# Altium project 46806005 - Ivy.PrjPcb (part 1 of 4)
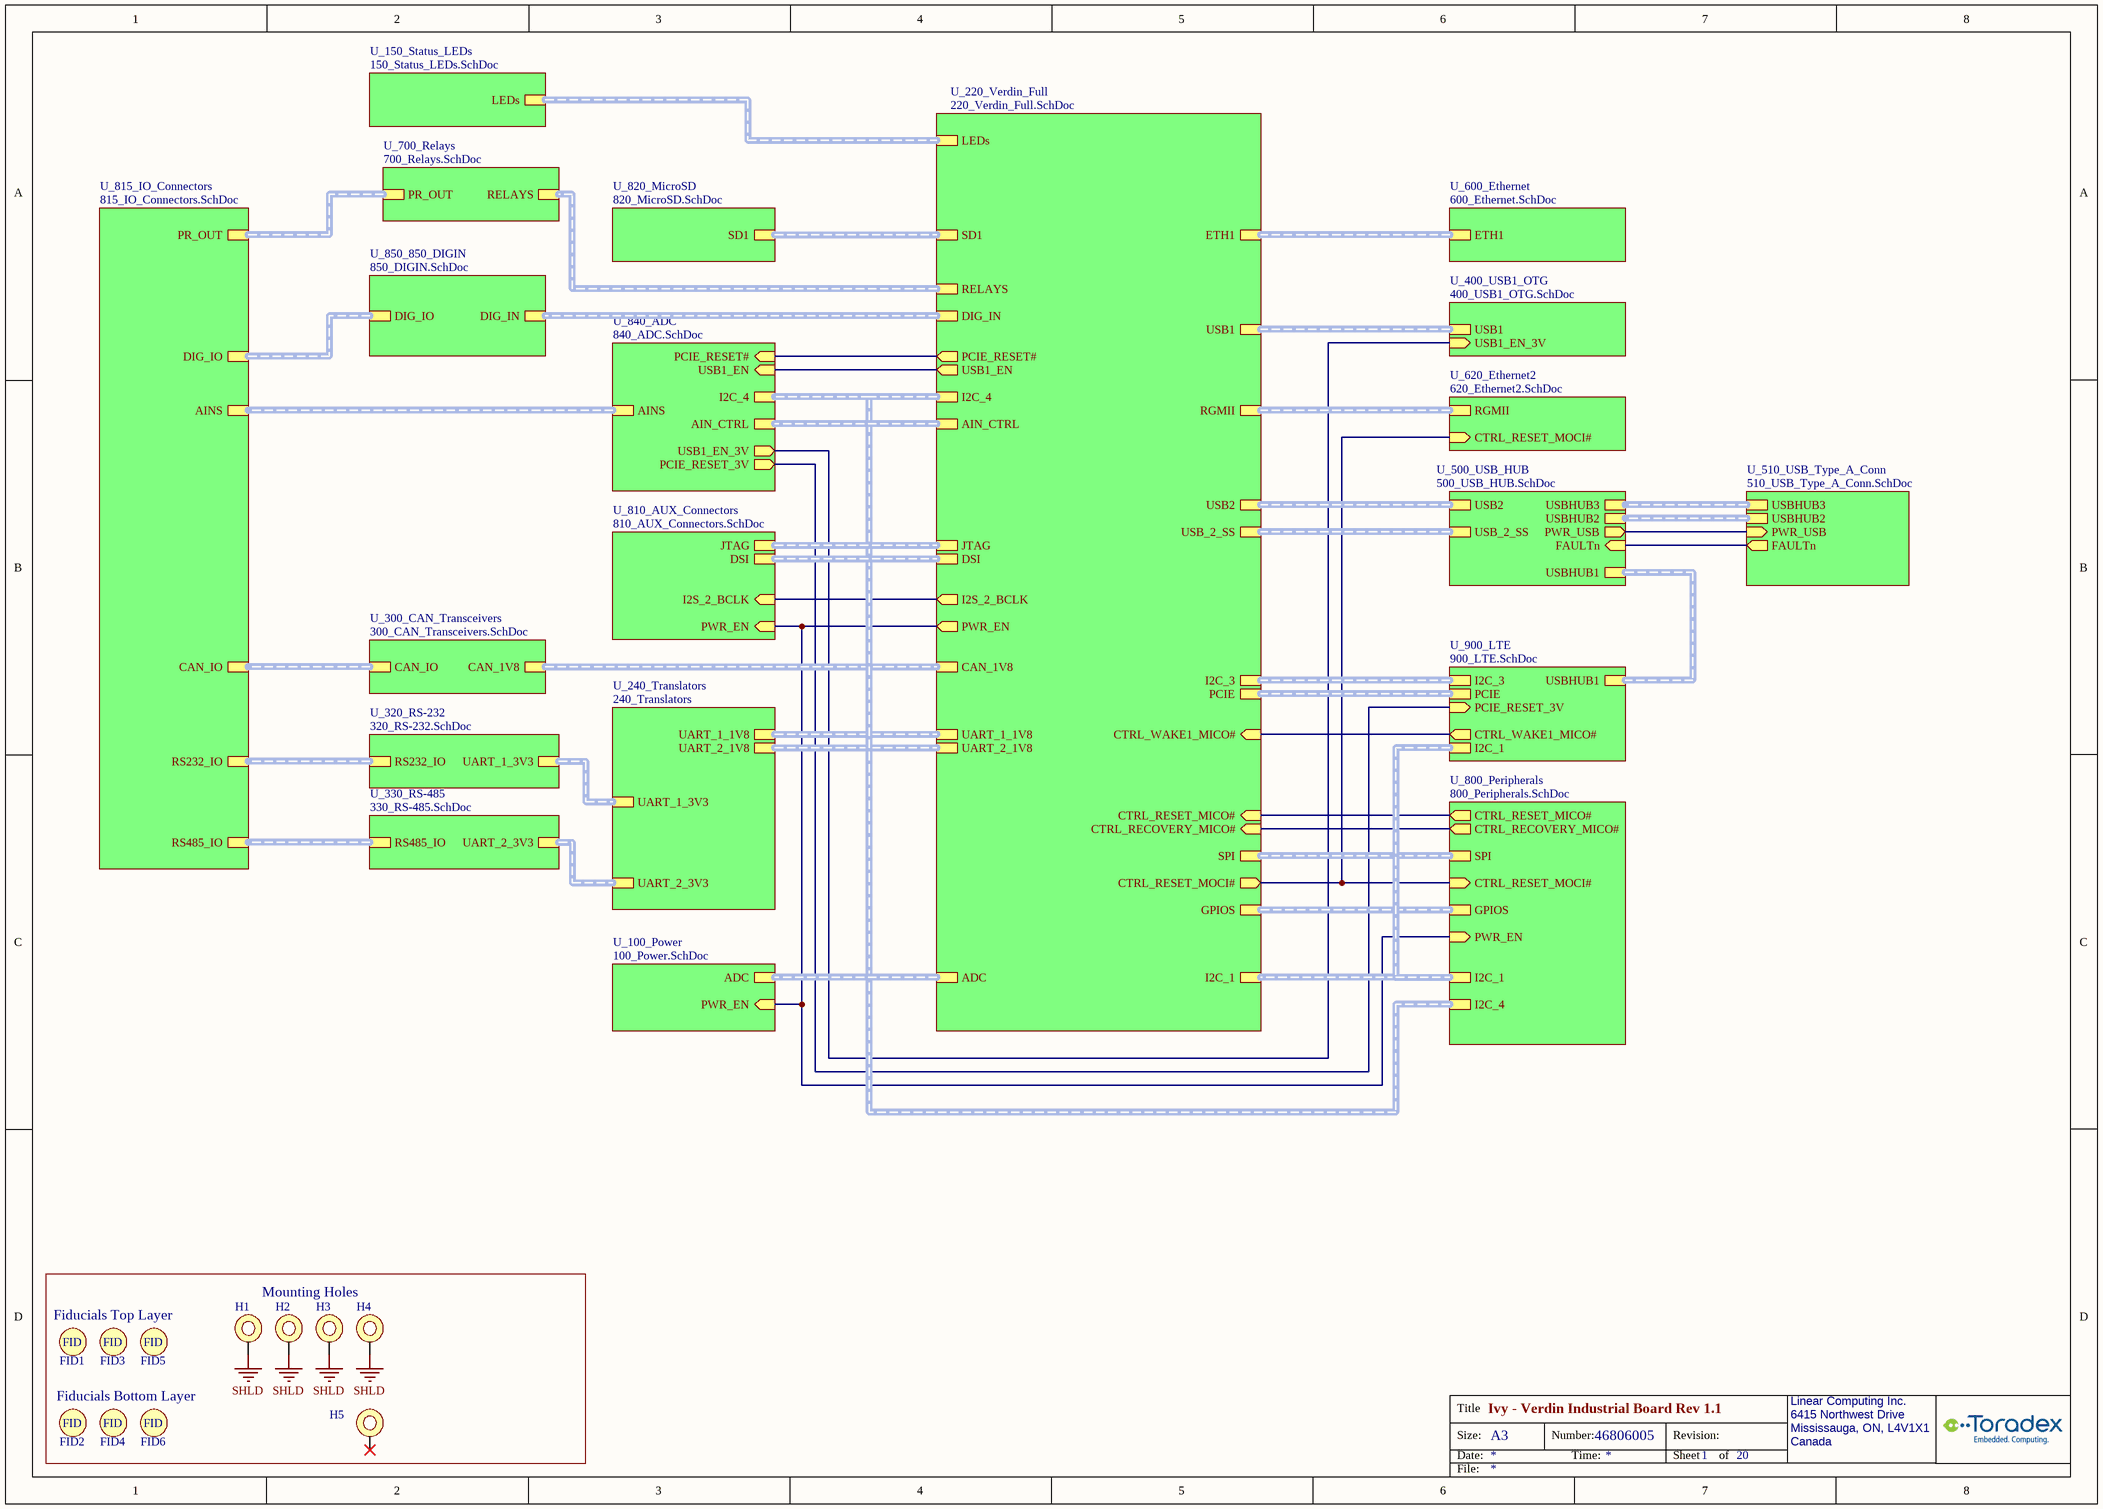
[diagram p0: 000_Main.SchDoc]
CompanyName: Toradex Solutions Inc.; DocumentNumber: 46806005; Title: Ivy - Verdin Industrial Board Rev 1.1
21 sheets, 800 parts. Net scope: hierarchical (ports join the sheet entries above them; power ports are global).
Board file: 46806005.PcbDoc
Sheets:
  000_Main.SchDoc
    U_100_Power = 100_Power.SchDoc
    U_600_Ethernet = 600_Ethernet.SchDoc
    U_400_USB1_OTG = 400_USB1_OTG.SchDoc
    U_220_Verdin_Full = 220_Verdin_Full.SchDoc
    U_800_Peripherals = 800_Peripherals.SchDoc
    U_240_Translators = 240_Translators.SchDoc
    U_900_LTE = 900_LTE.SchDoc
    U_300_CAN_Transceivers = 300_CAN_Transceivers.SchDoc
    U_500_USB_HUB = 500_USB_Hub.SchDoc
    U_700_Relays = 700_Relays.SchDoc
    U_150_Status_LEDs = 150_Status_LEDs.SchDoc
    U_620_Ethernet2 = 620_Ethernet2.SchDoc
    U_820_MicroSD = 820_MicroSD.SchDoc
    U_840_ADC = 840_ADC.SchDoc
    U_320_RS-232 = 320_RS-232.SchDoc
    U_330_RS-485 = 330_RS-485.SchDoc
    U_850_850_DIGIN = 850_DIGIN.SchDoc
    U_810_AUX_Connectors = 810_AUX_Connectors.SchDoc
    U_510_USB_Type_A_Conn = 510_USB_Type_A_Conn.SchDoc
    U_815_IO_Connectors = 815_IO_Connectors.SchDoc

## Sheet 000_Main.SchDoc: Ivy - Verdin Industrial Board Rev 1.1
size A3; Organization: Linear Computing Inc.; Address1: 6415 Northwest Drive; Address2: Mississauga, ON, L4V1X1; Address3: Canada; SheetNumber: 1; SheetTotal: 20

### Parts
FID1  Fiducial round  [FID_40X120_RND]  (value not drawn)  (no BOM)
FID2  Fiducial round  [FID_40X120_RND]  (value not drawn)  (no BOM)
FID3  Fiducial round  [FID_40X120_RND]  (value not drawn)  (no BOM)
FID4  Fiducial round  [FID_40X120_RND]  (value not drawn)  (no BOM)
FID5  Fiducial round  [FID_40X120_RND]  (value not drawn)  (no BOM)
FID6  Fiducial round  [FID_40X120_RND]  (value not drawn)  (no BOM)
H1  Hole  [MTG_HOLE_0.125]  (value not drawn)  (no BOM)
H2  Hole  [MTG_HOLE_0.125]  (value not drawn)  (no BOM)
H3  Hole  [MTG_HOLE_0.125]  (value not drawn)  (no BOM)
H4  Hole  [MTG_HOLE_0.125]  (value not drawn)  (no BOM)
H5  Hole  [MTG_HOLE_0.125]  (value not drawn)  (no BOM)

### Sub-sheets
U_100_Power = 100_Power.SchDoc: PWR_EN (in), ADC (harness ADC)
U_150_Status_LEDs = 150_Status_LEDs.SchDoc: LEDs (harness LEDs)
U_220_Verdin_Full = 220_Verdin_Full.SchDoc: CTRL_RECOVERY_MICO# (in), CTRL_RESET_MICO# (in), CTRL_WAKE1_MICO# (in), ETH1 (harness ETH1), USB2 (harness USB2), USB1 (harness USB1), PCIE (harness PCIe), SPI (harness SPI), PWR_EN (out), AIN_CTRL (harness AIN_CTRL), CTRL_RESET_MOCI# (out), GPIOS (harness GPIOs), RGMII (harness RGMII), SD1 (harness SD1), CAN_1V8 (harness 2xCAN_1V8), UART_1_1V8 (harness UART_1_1V8), UART_2_1V8 (harness UART_2_1V8), RELAYS (harness RELAYS), I2C_1 (harness I2C_1), DIG_IN (harness DIG_IN), JTAG (harness JTAG), LEDs (harness LEDs), I2C_4 (harness I2C_4), DSI (harness DSI), I2S_2_BCLK (out), ADC (harness ADC), I2C_3 (harness I2C_3), USB1_EN (out), PCIE_RESET# (out), USB_2_SS (harness USB_2_SS)
U_240_Translators = 240_Translators: UART_1_1V8 (harness UART_1_1V8), UART_2_1V8 (harness UART_2_1V8), UART_2_3V3 (harness UART_2_3V3), UART_1_3V3 (harness UART_1_3V3)
U_300_CAN_Transceivers = 300_CAN_Transceivers.SchDoc: CAN_1V8 (harness 2xCAN_1V8), CAN_IO (harness CAN_IO)
U_320_RS-232 = 320_RS-232.SchDoc: UART_1_3V3 (harness UART_1_3V3), RS232_IO (harness RS232_IO)
U_330_RS-485 = 330_RS-485.SchDoc: UART_2_3V3 (harness UART_2_3V3), RS485_IO (harness RS485_IO)
U_400_USB1_OTG = 400_USB1_OTG.SchDoc: USB1_EN_3V (in), USB1 (harness USB1)
U_500_USB_HUB = 500_USB_HUB.SchDoc: USB2 (harness USB2), USBHUB1 (harness USBHUB1), USBHUB2 (harness USBHUB2), USBHUB3 (harness USBHUB3), PWR_USB (out), FAULTn (in), USB_2_SS (harness USB_2_SS)
U_510_USB_Type_A_Conn = 510_USB_Type_A_Conn.SchDoc: USBHUB2 (harness USBHUB2), USBHUB3 (harness USBHUB3), PWR_USB (in), FAULTn (out)
U_600_Ethernet = 600_Ethernet.SchDoc: ETH1 (harness ETH1)
U_620_Ethernet2 = 620_Ethernet2.SchDoc: RGMII (harness RGMII), CTRL_RESET_MOCI# (in)
U_700_Relays = 700_Relays.SchDoc: RELAYS (harness RELAYS), PR_OUT (harness PR_OUT)
U_800_Peripherals = 800_Peripherals.SchDoc: CTRL_RECOVERY_MICO# (out), CTRL_RESET_MICO# (out), I2C_1 (harness I2C_1), SPI (harness SPI), I2C_4 (harness I2C_4), PWR_EN (in), CTRL_RESET_MOCI# (in), GPIOS (harness GPIOs)
U_810_AUX_Connectors = 810_AUX_Connectors.SchDoc: JTAG (harness JTAG), DSI (harness DSI), I2S_2_BCLK (in), PWR_EN (in)
U_815_IO_Connectors = 815_IO_Connectors.SchDoc: PR_OUT (harness PR_OUT), DIG_IO (harness DIG_IO), AINS (harness AINS), CAN_IO (harness CAN_IO), RS232_IO (harness RS232_IO), RS485_IO (harness RS485_IO)
U_820_MicroSD = 820_MicroSD.SchDoc: SD1 (harness SD1)
U_840_ADC = 840_ADC.SchDoc: I2C_4 (harness I2C_4), AIN_CTRL (harness AIN_CTRL), AINS (harness AINS), USB1_EN (in), PCIE_RESET# (in), USB1_EN_3V (out), PCIE_RESET_3V (out)
U_850_850_DIGIN = 850_DIGIN.SchDoc: DIG_IN (harness DIG_IN), DIG_IO (harness DIG_IO)
U_900_LTE = 900_LTE.SchDoc: PCIE (harness PCIe), CTRL_WAKE1_MICO# (out), PCIE_RESET_3V (in), USBHUB1 (harness USBHUB1), I2C_1 (harness I2C_1), I2C_3 (harness I2C_3)

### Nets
SHLD: H1.0(MTG_HOLE) H2.0(MTG_HOLE) H3.0(MTG_HOLE) H4.0(MTG_HOLE)
CTRL_RECOVERY_MICO#: sheet U_220_Verdin_Full/CTRL_RECOVERY_MICO#, sheet U_800_Peripherals/CTRL_RECOVERY_MICO#
CTRL_RESET_MICO#: sheet U_220_Verdin_Full/CTRL_RESET_MICO#, sheet U_800_Peripherals/CTRL_RESET_MICO#
CTRL_RESET_MOCI#: sheet U_220_Verdin_Full/CTRL_RESET_MOCI#, sheet U_800_Peripherals/CTRL_RESET_MOCI#, sheet U_620_Ethernet2/CTRL_RESET_MOCI#
CTRL_WAKE1_MICO#: sheet U_220_Verdin_Full/CTRL_WAKE1_MICO#, sheet U_900_LTE/CTRL_WAKE1_MICO#
FAULTn: sheet U_500_USB_HUB/FAULTn, sheet U_510_USB_Type_A_Conn/FAULTn
I2S_2_BCLK: sheet U_220_Verdin_Full/I2S_2_BCLK, sheet U_810_AUX_Connectors/I2S_2_BCLK
PCIE_RESET#: sheet U_220_Verdin_Full/PCIE_RESET#, sheet U_840_ADC/PCIE_RESET#
PCIE_RESET_3V: sheet U_900_LTE/PCIE_RESET_3V, sheet U_840_ADC/PCIE_RESET_3V
PWR_EN: sheet U_100_Power/PWR_EN, sheet U_220_Verdin_Full/PWR_EN, sheet U_800_Peripherals/PWR_EN, sheet U_810_AUX_Connectors/PWR_EN
PWR_USB: sheet U_500_USB_HUB/PWR_USB, sheet U_510_USB_Type_A_Conn/PWR_USB
USB1_EN: sheet U_220_Verdin_Full/USB1_EN, sheet U_840_ADC/USB1_EN
USB1_EN_3V: sheet U_400_USB1_OTG/USB1_EN_3V, sheet U_840_ADC/USB1_EN_3V

Not connected (* = marked no-connect by the designer): H5 0(MTG_HOLE)*

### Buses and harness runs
harness sheet U_100_Power/ADC = sheet U_220_Verdin_Full/ADC
harness sheet U_150_Status_LEDs/LEDs = sheet U_220_Verdin_Full/LEDs
harness sheet U_220_Verdin_Full/AIN_CTRL = sheet U_840_ADC/AIN_CTRL
harness sheet U_220_Verdin_Full/CAN_1V8 = sheet U_300_CAN_Transceivers/CAN_1V8
harness sheet U_220_Verdin_Full/DIG_IN = sheet U_850_850_DIGIN/DIG_IN
harness sheet U_220_Verdin_Full/DSI = sheet U_810_AUX_Connectors/DSI
harness sheet U_220_Verdin_Full/ETH1 = sheet U_600_Ethernet/ETH1
harness sheet U_220_Verdin_Full/GPIOS = sheet U_800_Peripherals/GPIOS
harness sheet U_220_Verdin_Full/I2C_1 = sheet U_800_Peripherals/I2C_1 = sheet U_900_LTE/I2C_1
harness sheet U_220_Verdin_Full/I2C_3 = sheet U_900_LTE/I2C_3
harness sheet U_220_Verdin_Full/I2C_4 = sheet U_800_Peripherals/I2C_4 = sheet U_840_ADC/I2C_4
harness sheet U_220_Verdin_Full/JTAG = sheet U_810_AUX_Connectors/JTAG
harness sheet U_220_Verdin_Full/PCIE = sheet U_900_LTE/PCIE
harness sheet U_220_Verdin_Full/RELAYS = sheet U_700_Relays/RELAYS
harness sheet U_220_Verdin_Full/RGMII = sheet U_620_Ethernet2/RGMII
harness sheet U_220_Verdin_Full/SD1 = sheet U_820_MicroSD/SD1
harness sheet U_220_Verdin_Full/SPI = sheet U_800_Peripherals/SPI
harness sheet U_220_Verdin_Full/UART_1_1V8 = sheet U_240_Translators/UART_1_1V8
harness sheet U_220_Verdin_Full/UART_2_1V8 = sheet U_240_Translators/UART_2_1V8
harness sheet U_220_Verdin_Full/USB1 = sheet U_400_USB1_OTG/USB1
harness sheet U_220_Verdin_Full/USB2 = sheet U_500_USB_HUB/USB2
harness sheet U_220_Verdin_Full/USB_2_SS = sheet U_500_USB_HUB/USB_2_SS
harness sheet U_240_Translators/UART_1_3V3 = sheet U_320_RS-232/UART_1_3V3
harness sheet U_240_Translators/UART_2_3V3 = sheet U_330_RS-485/UART_2_3V3
harness sheet U_300_CAN_Transceivers/CAN_IO = sheet U_815_IO_Connectors/CAN_IO
harness sheet U_320_RS-232/RS232_IO = sheet U_815_IO_Connectors/RS232_IO
harness sheet U_330_RS-485/RS485_IO = sheet U_815_IO_Connectors/RS485_IO
harness sheet U_500_USB_HUB/USBHUB1 = sheet U_900_LTE/USBHUB1
harness sheet U_500_USB_HUB/USBHUB2 = sheet U_510_USB_Type_A_Conn/USBHUB2
harness sheet U_500_USB_HUB/USBHUB3 = sheet U_510_USB_Type_A_Conn/USBHUB3
harness sheet U_700_Relays/PR_OUT = sheet U_815_IO_Connectors/PR_OUT
harness sheet U_815_IO_Connectors/AINS = sheet U_840_ADC/AINS
harness sheet U_815_IO_Connectors/DIG_IO = sheet U_850_850_DIGIN/DIG_IO

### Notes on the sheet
- Fiducials Top Layer
- Mounting Holes
- Fiducials Bottom Layer

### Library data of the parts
FID1-FID6 = 0000-Fiducial-round
H1-H5 = 000-Hole-125mil

## Sheet 100_Power.SchDoc: Ivy - Verdin Industrial Board Rev 1.1
size Letter; Organization: Toradex Solutions Inc.; Address1: 6415 Northwest Drive; Address2: Mississauga, ON, L4V 1X1; Address3: Canada
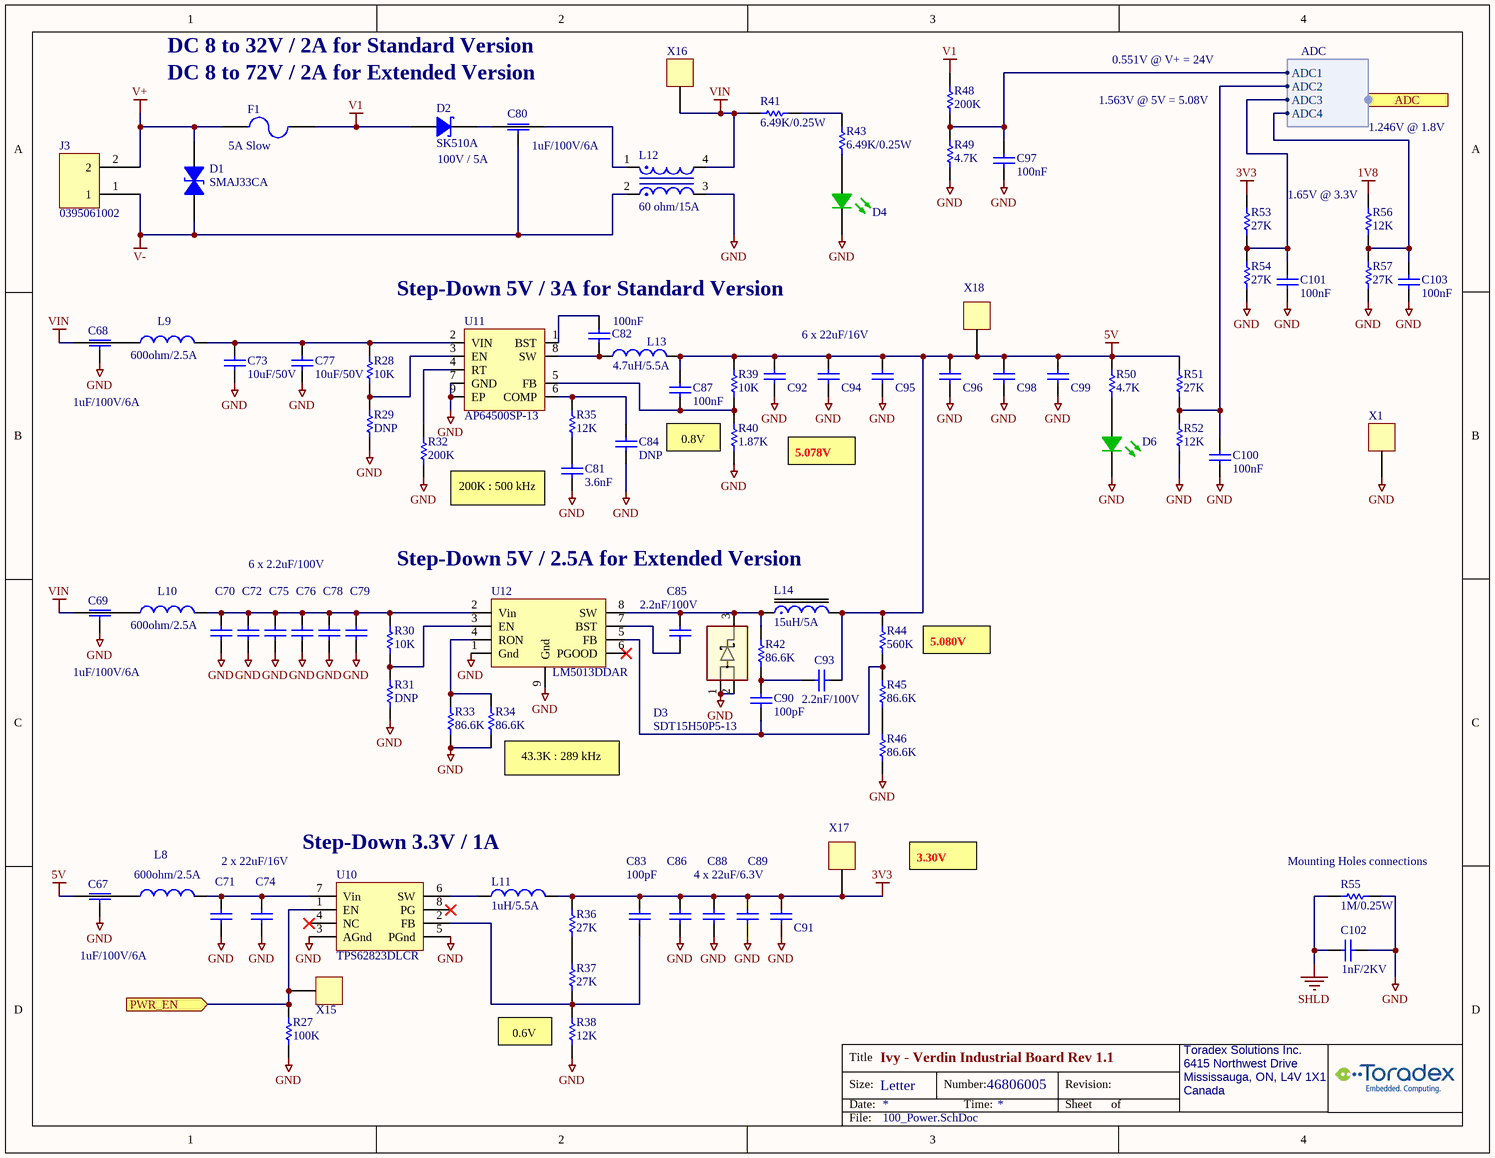
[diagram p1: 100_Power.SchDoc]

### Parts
C67  value 1uF/100V/6A  [C/1206_3P]  (hidden comment: 0753-Cap 3P-1206-1uF/100V/6A)
C68  value 1uF/100V/6A  [C/1206_3P]  (hidden comment: 0753-Cap 3P-1206-1uF/100V/6A)
C69  value 1uF/100V/6A  [C/1206_3P]  (hidden comment: 0753-Cap 3P-1206-1uF/100V/6A)
C70  CC1206KKX7R0BB225  [C/1206]  (value not drawn)
C71  1314-Cap-0805-22uF/16V  [C/0805]  (value not drawn)
C72  CC1206KKX7R0BB225  [C/1206]  (value not drawn)
C73  10uF/50V  [CAPC3225N]
C74  1314-Cap-0805-22uF/16V  [C/0805]  (value not drawn)
C75  CC1206KKX7R0BB225  [C/1206]  (value not drawn)
C76  CC1206KKX7R0BB225  [C/1206]  (value not drawn)
C77  10uF/50V  [CAPC3225N]
C78  CC1206KKX7R0BB225  [C/1206]  (value not drawn)
C79  CC1206KKX7R0BB225  [C/1206]  (value not drawn)
C80  value 1uF/100V/6A  [C/1206_3P]  (hidden comment: 0753-Cap 3P-1206-1uF/100V/6A)
C81  value 3.6nF  [C/0603]  (hidden comment: 1470-Cap-0603-3.6nF)
C82  100nF  [C0402_CAPC1005L]
C83  value 100pF  [C0402_CAPC1005L]  (hidden comment: 1602-Cap-0402-100pF)
C84  value DNP  [C/0603]  (hidden comment: 0000-Cap-0603-DNP)
C85  value 2.2nF/100V  [C/0603]  (hidden comment: 1875-Cap-0603-2.2nF/100V)
C86  22uF/6.3V  [C0402_CAPC1005L]  (value not drawn)
C87  value 100nF  [C0402_CAPC1005L]  (hidden comment: 1566-Cap-0402-100nF/50V)
C88  22uF/6.3V  [C0402_CAPC1005L]  (value not drawn)
C89  22uF/6.3V  [C0402_CAPC1005L]  (value not drawn)
C90  value 100pF  [C0402_CAPC1005L]  (hidden comment: 1602-Cap-0402-100pF)
C91  22uF/6.3V  [C0402_CAPC1005L]  (value not drawn)
C92  1314-Cap-0805-22uF/16V  [C/0805]  (value not drawn)
C93  value 2.2nF/100V  [C/0603]  (hidden comment: 1875-Cap-0603-2.2nF/100V)
C94  1314-Cap-0805-22uF/16V  [C/0805]  (value not drawn)
C95  1314-Cap-0805-22uF/16V  [C/0805]  (value not drawn)
C96  1314-Cap-0805-22uF/16V  [C/0805]  (value not drawn)
C97  100nF  [C0402_CAPC1005L]
C98  1314-Cap-0805-22uF/16V  [C/0805]  (value not drawn)
C99  1314-Cap-0805-22uF/16V  [C/0805]  (value not drawn)
C100  100nF  [C0402_CAPC1005L]
C101  100nF  [C0402_CAPC1005L]
C102  value 1nF/2KV  [C/1206]  (hidden comment: 0567-Cap-1206-1nF/2KV)
C103  100nF  [C0402_CAPC1005L]
D1  SMAJ33CA  [SMAJ_TRANSIL]
D2  SK510A  [SMAJ]
D3  SDT15H50P5-13  [POWERDI-5_DIO]
D4  Status  [LED-SMT-0603_APT1608CGCK]  (value not drawn)
D6  Status  [LED-SMT-0603_APT1608CGCK]  (value not drawn)
F1  5A Slow  [FUSC6125X279N]
J3  0395061002  [Phoenix_1727566]
L8  value 600ohm/2.5A  [INDP1206]  (hidden comment: 1641-Fer-1206-600ohm/2.5A)
L9  value 600ohm/2.5A  [INDP1206]  (hidden comment: 1641-Fer-1206-600ohm/2.5A)
L10  value 600ohm/2.5A  [INDP1206]  (hidden comment: 1641-Fer-1206-600ohm/2.5A)
L11  value 1uH/5.5A  [INDC3225N]  (hidden comment: NS10165T4R7NNA)
L12  60 ohm/15A  [COMMON_CHOKE_Laird_CM3421Y600R-10]
L13  value 4.7uH/5.5A  [INDP_7.3X6.6N]  (hidden comment: BMRA000606304R7MA1)
L14  value 15uH/5A  [EATON_DR127]  (hidden comment: DR127-150-R)
R27  value 100K  [R0402_RESC1005L]  (hidden comment: 1977-Res-0402-100K)
R28  value 10K  [R0402_RESC1005L]  (hidden comment: 1572-Res-0402-10K)
R29  value DNP  [R/0603]  (hidden comment: 0000-Res-0603-DNP)
R30  value 10K  [R0402_RESC1005L]  (hidden comment: 1572-Res-0402-10K)
R31  value DNP  [R/0603]  (hidden comment: 0000-Res-0603-DNP)
R32  value 200K  [R/0603]  (hidden comment: 1367-Res-0603-200K)
R33  value 86.6K  [R0402_RESC1005L]  (hidden comment: 1539-Res-0402-86.6k)
R34  value 86.6K  [R0402_RESC1005L]  (hidden comment: 1539-Res-0402-86.6k)
R35  value 12K  [R0402_RESC1005L]  (hidden comment: 1537-Res-0402-12K)
R36  value 27K  [R0402_RESC1005L]  (hidden comment: 1538-Res-0402-27k)
R37  value 27K  [R0402_RESC1005L]  (hidden comment: 1538-Res-0402-27k)
R38  value 12K  [R0402_RESC1005L]  (hidden comment: 1537-Res-0402-12K)
R39  value 10K  [R0402_RESC1005L]  (hidden comment: 1572-Res-0402-10K)
R40  value 1.87K  [R0402_RESC1005L]  (hidden comment: 1536-Res-0402-1.87K)
R41  value 6.49K/0.25W  [R/0805]  (hidden comment: 1603-Res-0805-6.49K/0.25W)
R42  value 86.6K  [R0402_RESC1005L]  (hidden comment: 1539-Res-0402-86.6k)
R43  value 6.49K/0.25W  [R/0805]  (hidden comment: 1603-Res-0805-6.49K/0.25W)
R44  value 560K  [R/0603]  (hidden comment: 1876-Res-0603-560K)
R45  value 86.6K  [R0402_RESC1005L]  (hidden comment: 1539-Res-0402-86.6k)
R46  value 86.6K  [R0402_RESC1005L]  (hidden comment: 1539-Res-0402-86.6k)
R48  value 200K  [R/0603]  (hidden comment: 1367-Res-0603-200K)
R49  value 4.7K  [R0402_RESC1005L]  (hidden comment: 2233-Res-0402-4.7K)
R50  value 4.7K  [R0402_RESC1005L]  (hidden comment: 2233-Res-0402-4.7K)
R51  value 27K  [R0402_RESC1005L]  (hidden comment: 1538-Res-0402-27k)
R52  value 12K  [R0402_RESC1005L]  (hidden comment: 1537-Res-0402-12K)
R53  value 27K  [R0402_RESC1005L]  (hidden comment: 1538-Res-0402-27k)
R54  value 27K  [R0402_RESC1005L]  (hidden comment: 1538-Res-0402-27k)
R55  value 1M/0.25W  [R/1206]  (hidden comment: 1860-Res-1206-1M-5%-0.25W)
R56  value 12K  [R0402_RESC1005L]  (hidden comment: 1537-Res-0402-12K)
R57  value 27K  [R0402_RESC1005L]  (hidden comment: 1538-Res-0402-27k)
U10  TPS62823DLCR  [DLC0008A]
U11  AP64500SP-13  [SOP-9 TP_ALT]
U12  LM5013DDAR  [SOP-9 TP]
X1  000-TestPoint  [TestPoint_1]  (value not drawn)
X15  000-TestPoint  [TestPoint_1]  (value not drawn)
X16  000-TestPoint  [TestPoint_1]  (value not drawn)
X17  000-TestPoint  [TestPoint_1]  (value not drawn)
X18  000-TestPoint  [TestPoint_1]  (value not drawn)

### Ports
ADC (harness ADC), PWR_EN (in)

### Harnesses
ADC: ADC1, ADC2, ADC3, ADC4

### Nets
1V8: R56.2
3V3: C83.2 C86.2 C88.2 C89.2 C91.2 L11.2 R36.2 R53.2 X17.1
5V: C67.1(In/Out) C87.2 C92.2 C93.2 C94.2 C95.2 C96.2 C98.2 C99.2 L13.2 L14.2 R39.2 R44.2 R50.2 R51.2 X18.1
GND: C67.2(Gnd) C68.2(Gnd) C69.2(Gnd) C70.1 C71.1 C72.1 C73.1 C74.1 C75.1 C76.1 C77.1 C78.1 C79.1 C81.2 C84.2 C86.1 C88.1 C89.1 C91.1 C92.1 C94.1 C95.1 C96.1 C97.2 C98.1 C99.1 C100.2 C101.2 C102.1 C103.2 D3.1 D3.2 D4.2(K) D6.2(K) L12.3 R27.1 R29.2 R31.2 R32.1 R33.1 R34.1 R38.1 R40.1 R46.1 R49.1 R52.1 R54.1 R55.2 R57.1 U10.3(AGnd) U10.5(PGnd) U11.7(GND) U11.9(EP) U12.1(Gnd) U12.9(Gnd) X1.1
SHLD: C102.2 R55.1
V1: D2.1(A) F1.2 R48.2
V+: D1.2 F1.1 J3.2
V-: C80.2(Gnd) D1.1 J3.1 L12.2
VIN: C68.1(In/Out) C69.1(In/Out) L12.4 R41.1 X16.1
PWR_EN: R27.2 U10.1(EN) X15.1 ; port PWR_EN
NetC67_3: C67.3(In/Out) L8.1
NetC68_3: C68.3(In/Out) L9.1
NetC69_3: C69.3(In/Out) L10.1
NetC70_2: C70.2 C72.2 C75.2 C76.2 C78.2 C79.2 L10.2 R30.2 U12.2(Vin)
NetC71_2: C71.2 C74.2 L8.2 U10.7(Vin)
NetC73_2: C73.2 C77.2 L9.2 R28.2 U11.2(VIN)
NetC80_1: C80.1(In/Out) D2.2(K)
NetC80_3: C80.3(In/Out) L12.1
NetC81_1: C81.1 R35.1
NetC82_1: C82.1 U11.1(BST)
NetC82_2: C82.2 L13.1 U11.8(SW)
NetC83_1: C83.1 R37.1 R38.2 U10.2(FB)
NetC84_1: C84.1 R35.2 U11.6(COMP)
NetC85_1: C85.1 D3.3 L14.1 R42.2 U12.8(SW)
NetC85_2: C85.2 U12.7(BST)
NetC87_1: C87.1 R39.1 R40.2 U11.5(FB)
NetC90_1: C90.1 R44.1 R45.2 U12.5(FB)
NetC90_2: C90.2 C93.1 R42.1
NetC97_1: C97.1 R48.1 R49.2 ; port ADC.ADC1
NetC100_1: C100.1 R51.1 R52.2 ; port ADC.ADC2
NetC101_1: C101.1 R53.1 R54.2 ; port ADC.ADC3
NetC103_1: C103.1 R56.1 R57.2 ; port ADC.ADC4
NetD4_1: D4.1(A) R43.2
NetD6_1: D6.1(A) R50.1
NetL11_1: L11.1 U10.6(SW)
NetR28_1: R28.1 R29.1 U11.3(EN)
NetR30_1: R30.1 R31.1 U12.3(EN)
NetR32_2: R32.2 U11.4(RT)
NetR33_2: R33.2 R34.2 U12.4(RON)
NetR36_1: R36.1 R37.2
NetR41_2: R41.2 R43.1
NetR45_1: R45.1 R46.2

Not connected (* = marked no-connect by the designer): U10 4(NC)* 8(PG)*; U12 6(PGOOD)*

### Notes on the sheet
- DC 8 to 32V / 2A for Standard Version
- DC 8 to 72V / 2A for Extended Version
- 1.563V @ 5V = 5.08V
- 0.551V @ V+ = 24V
- 100V / 5A
- 1.246V @ 1.8V
- (near R56) 1.65V @ 3.3V
- Step-Down 5V / 3A for Standard Version
- 6 x 22uF/16V
- 200K : 500 kHz
- (near R40) 0.8V
- 5.078V
- 6 x 2.2uF/100V
- Step-Down 5V / 2.5A for Extended Version
- 5.080V
- (near R34) 43.3K : 289 kHz
- 2 x 22uF/16V
- Step-Down 3.3V / 1A
- 4 x 22uF/6.3V
- 3.30V
- (near R55) Mounting Holes connections
- 0.6V

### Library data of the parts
C67-C69 C80 = 0753-Cap 3P-1206-1uF/100V/6A: (-55 to 125 DegC) CAP FEEDTHRU 1UF 20% 100V 1206 6A; Mfr: TDK Corporation; MfrNo: YFF31HC2A105MT000N; PN: 753; Alt: YFF31AH2A105MT0Y0N
C70 C72 C75 C76 C78 C79 = 1873-Cap-1206-2.2uF/100V: (-55 to 125 DegC) CAP CER 2.2UF 100V 10% X7R 1206; Mfr: Yageo; PN: 1873
C71 C74 C92 C94-C96 C98 C99 = 1314-Cap-0805-22uF/16V: (-55 to 85 DegC) CAP CER 22uF 16V X5R 0805; MfrNo: CL21A226MOQNNNE; Mfr: Samsung; PN: 1314; Alt: CL21A226MOCLRNC,CL21A226KOQNNNG,GRM21BR61C226ME44L,EMK212BBJ226MG-T
C73 C77 = 1607-Cap-1206-10uF/50V: (-55 to 85 DegC) CAP CER 10UF 50V 10% X5R 1210; Mfr: Samsung; MfrNo: CL31A106KBHNNNE; Alt: CL31A106MBHNNNE,UMK316BBJ106ML-T,UMK316BBJ106KL-T,GRT31CR61H106ME01L,MSASU31LBB5106MTNA01; PN: 1607
C81 = 1470-Cap-0603-3.6nF: (-55 to 125 DegC) CAP CER 3600PF 50V C0G/NP0 0603; Mfr: Murata; MfrNo: GRM1885C1H362JA01D; Alt: GCM1885C1H362FA16J,C0603C362J5GAC7867,C0603C362F5GAC7867; PN: 1470
C82 C97 C100 C101 C103 = 1566-Cap-0402-100nF/50V: (-55 to 125 DegC AEC) Cap Ceramic 0.1uF 50V X7R 10% 0402; MfrNo: GRT155R71H104KE01D; Mfr: Murata; Alt: CL05B104KB54PNC,GCM155R71H104ME02D,GCM155R71H104KE02D,GCM155R71H104KE02J; PN: 1566
C83 = 1602-Cap-0402-100pF: (-55 to 125 Degc AEC) CAP CER 100PF 50V 5% NPO 0402; MfrNo: GCM1555C1H101JA16D; Mfr: Murata; PN: 1602; Alt: UMK105CH101JVHF,GRT1555C1H101JA02D,GRT1555C1H101JA02J,CL05C101JB51PNC
C84 = 0000-Cap-0603-DNP: Cap 0603 DNP
C85 C93 = 1875-Cap-0603-2.2nF/100V: (-55 to 125 DegC) CAP CER 2.2nF 100V 10% X7R 0603; Mfr: KEMET; MfrNo: C0603C222K1RACTU; PN: 1875
C86 C88 C89 C91 = 2404-Cap-0402-22uF/6.3V: (-55 to 85 DegC) CAP CER 22UF 6.3V 20% X5R 0402; MfrNo: GRM155R60J226ME11D; Mfr: Murata; PN: 2404
C87 = 1566-Cap-0402-100nF/50V: (-55 to 125 DegC AEC) Cap Ceramic 0.1uF 50V X7R 10% 0402; Mfr: Murata; MfrNo: GRT155R71H104KE01D; Alt: CL05B104KB54PNC,GCM155R71H104ME02D,GCM155R71H104KE02D,GCM155R71H104KE02J; PN: 1566
C90 = 1602-Cap-0402-100pF: (-55 to 125 Degc AEC) CAP CER 100PF 50V 5% NPO 0402; Mfr: Murata; MfrNo: GCM1555C1H101JA16D; PN: 1602; Alt: UMK105CH101JVHF,GRT1555C1H101JA02D,GRT1555C1H101JA02J,CL05C101JB51PNC
C102 = 0567-Cap-1206-1nF/2KV: CAP CER 1000PF 2KV X7R 1206; Mfr: Johanson Dielectrics Inc.; MfrNo: 202R18W102KV4E; PN: 567; Alt: 478-2956-1-ND; Alt2: 399-4819-1-ND
D1 = 0581-SMAJ33CA: (-55 to 150 DegC) TVS DIODE 33VWM Vbrm:36.7V Vcl:53.3V 400W SMA; Mfr: Vishay Semiconductor Diodes Division; MfrNo: SMAJ33CA-E3/5A; PN: 581; Desc: (-55 to 150 DegC) TVS DIODE 33VWM Vbrm:36.7V Vstd:53.3VC SMA; Alt: SMAJ33CA-E3/61GICT-ND; Alt2: SMAJ33CABCT-ND; DR: SMAJ33CA-E3/5AGIDKR-ND; DR2: 625-SMAJ33CA-E3/5A
D2 = 1164-SK510A: (-55 to 150 DegC) DIODE SCHOTTKY 5A 100V DO-214AC SMA 850mV@5A; MfrNo: SK510A-LTP; Mfr: MCC; PN: 1164; Alt: CDBA5100-HF; Note: similar in SMB: SK510B-LTP
D3 = 2201-SDT15H50P5-13: (-55 to 150 DegC) DIODE SCHOTTKY 15A 50V Vf:0.3V@1.5A 0.47V@15A SMA; Mfr: Diodes; PN: 2201
D4 D6 = 0333-LED Green 0603: (-40 to 85 DegC) LED GREEN 0603 50mcd; MfrNo: APT1608CGCK; Mfr: Kingbright; Alt: 754-1357-1-ND; Alt2: 160-1834-1-ND; PN: 333; DR: 754-1116-6-ND; DR2: 604-APT1608CGCK
F1 = 2235-Fuse 5A Slow 125V: (-55 to 125 DegC AEC) FUSE BOARD MOUNT 5A SLOW 125VAC/VDC; Mfr: Bel; MfrNo: 0680L5000-05; PN: 2235
J3 = 1195-Conn-Molex 2-POS R/A: (-40 to 105 DegC) TERM BLOCK HDR 2POS 90DEG RA 3.5MM 8A ScrewFlange Black; Mfr: Molex; PN: 1195; Note: plug: 0395040002,0395045002; Alt: green 0395066002
L8-L10 = 1641-Fer-1206-600ohm/2.5A: (-55 to 125 DegC AEC) FERRITE BEAD 600ohm 1206 2.5A 50mohm R@1A@150MHz:40.7ohm; Mfr: Wurth Electronics; MfrNo: 78279221601; PN: 1641; Notes: similar performance for 1A@150MHz: 742792116, 742792121, 782763301
L11 = 1618-Ind-1210-1uH/5.5A: (-40 to 125 DegC) FIXED IND 1UH I:5.5A Isat:6.5A 32mohm max 26mohm typ, full-shield SMD 1210; MfrNo: SRP3212-1R0M; Mfr: Bourns; PN: 1618; Alt: DFE322512F-1R0M=P2,DFE32CAH1R0MR0L,DFE322520F-1R0M=P2,DFE322520FD-1R0M=P2
L12 = 0598-Ind-10x6-60ohm/15A-Choke: (-40 to 125 DegC) CMC Choke 15A  60OHM 10x6x4mm 15A 0.7mohm; Mfr: Laird-Signal Integrity Products; MfrNo: CM3421Y600R-10; PN: 598; DR: 240-2501-6-ND; DR2: 875-CM3421Y600R-10
L13 = 1638-Ind-7x7x3-4.7uH-5.5A: (-55 to 125 DegC) FIXED IND 4.7UH FullShield 5.5A, 9A sat 40mohm 7.3x6.6x3.0mm; Mfr: Pulse; PN: 1638; Alt: PN1639, PN1640
L14 = 1872-Ind-12x12x8-15uH-5A: (-40 to 125 DegC) FIXED IND 15UH, 5A, 9.6A sat, 25mohm FullShield 12.5x12.5x8mm; Mfr: Eaton Cooper; PN: 1872
R27 = 1977-Res-0402-100K: (-55 to 155 DegC) RES 100K OHM 1/16W 1% 0402 SMD; Mfr: Yageo; MfrNo: RC0402FR-07100KL; PN: 1977
R28 R30 = 1572-Res-0402-10K: (-55 to 155 DegC AEC) RES 10K OHM 1% 1/16W 100ppm 0402; Mfr: Stackpole Electronics; MfrNo: RMCF0402FT10K0; PN: 1572; Alt: AC0402FR-0710KL,AC0402FR-1310KL,CRGCQ0402F10K
R29 R31 = 0000-Res-0603-DNP: RES 0603
R32 R48 = 1367-Res-0603-200K: (-55 to 155 DegC) RES SMD 200K 1% 1/10W 0603 100ppm; Mfr: Stackpole Electronics; MfrNo: RMCF0603FT200K; Alt: CR0603-FX-2003ELF,RC0603FR-07200KL,RK73H1JTTD2003F; PN: 1367
R33 R34 R42 R45 R46 = 1539-Res-0402-86.6k: (-55 to 155 DegC AEC) RES 86.6K OHM 1% 1/16W 100ppm 0402; Mfr: Stackpole Electronics; MfrNo: RMCF0402FT86K6; Alt: AC0402FR-0786K6L,RK73H1ETTP8662F,ERJ-2RKF8662X; PN: 1539
R35 R38 R52 R56 = 1537-Res-0402-12K: (-55 to 155 DegC AEC) RES 12K OHM 1% 1/16W 100ppm 0402; Mfr: Stackpole Electronics; MfrNo: RMCF0402FT12K0; Alt: AC0402FR-0712KL,CRGCQ0402F12K; PN: 1537
R36 R37 R51 R53 R54 R57 = 1538-Res-0402-27k: (-55 to 155 DegC AEC) RES 27K OHM 1% 1/16W 100ppm 0402; Mfr: Stackpole Electronics; MfrNo: RMCF0402FT27K0; PN: 1538; Alt: AC0402FR-0727KL,CRGCQ0402F27K
R39 = 1572-Res-0402-10K: (-55 to 155 DegC AEC) RES 10K OHM 1% 1/16W 100ppm 0402; Mfr: Stackpole Electronics; MfrNo: RMCF0402FT10K0; Alt: AC0402FR-0710KL,AC0402FR-1310KL,CRGCQ0402F10K; PN: 1572
R40 = 1536-Res-0402-1.87K: (-55 to 155 DegC AEC) RES 1.87K OHM 1% 1/16W 100ppm 0402; MfrNo: RMCF0402FT1K87; Mfr: Stackpole Electronics; Alt: AC0402FR-071K87L,RK73H1ETTP1871F,ERJ-2RKF1871X; PN: 1536
R41 R43 = 1603-Res-0805-6.49K/0.25W: (-55 to 155 DegC AEC) RES 6.49K OHM 1% 0.25W 0805 100ppm; Mfr: KOA Speer; MfrNo: RK73H2ATTD6491F; Alt: RCS08056K49FKEA,CRCW08056K49FKEAHP; PN: 1603
R44 = 1876-Res-0603-560K: (-55 to 155 DegC AEC) RES SMD 560K 1% 1/10W 0603 100ppm; Mfr: Stackpole Electronics; MfrNo: RMCF0603FT560K; PN: 1876
R49 R50 = 2233-Res-0402-4.7K: (-55 to 155 DegC) RES 4.70K OHM 1/16W 1% 0402 100ppm; MfrNo: RC0402FR-074K7L; Mfr: Yageo; PN: 2233
R55 = 1860-Res-1206-1M-5%-0.25W: (-55 to 155 DegC) RES SMD 1M OHM 5% 0.25W 10ppm 1206; Mfr: TE Connectivity; MfrNo: CRGCQ1206J1M0; PN: 1860; Alt: RMCF1206JT1M00, RMCF1206JG1M00, CR1206-JW-105ELF
U10 = 1619-TPS62823: (-40 to 125 DegC) IC  IC REG BUCK ADJ 2.2MHz Vin:2.4-5.5V Io:3A Sync 8-VFDFN 8VSON-HR; Mfr: Texas Instruments; PN: 1619; Alt: TPS62823DLCT; Note: similar with smaller output current: TPS62822DLC, TPS62821DLC
U11 = 1362-AP64500SP-13: (-40 to 85 DegC) IC REG BUCK ADJ Sync 5A Vin:3.8 to 40V 100-2200kHz FSS (spread spectrum) MaxDuty:100% SO-8EP; Mfr: Diodes; PN: 1362; Alt: AP64500QSP-13; Note: similar: AP64501 PN1392
U12 = 2063-LM5013DDAR: (-40 to 150 DegC) IC REG BUCK ADJ 3.5A 8-POWERSOIC 1MHz 100V; Mfr: Texas Instruments; PN: 2063
X1 X15-X18 = 000-TestPoint: Note: this is PCB footprint only, no parts to buy or assemble

## Sheet 600_Ethernet.SchDoc: Ivy - Verdin Industrial Board Rev 1.1
size Letter; Organization: Toradex Solutions Inc.; Address1: 6415 Northwest Drive; Address2: Mississauga, ON, L4V 1X1; Address3: Canada
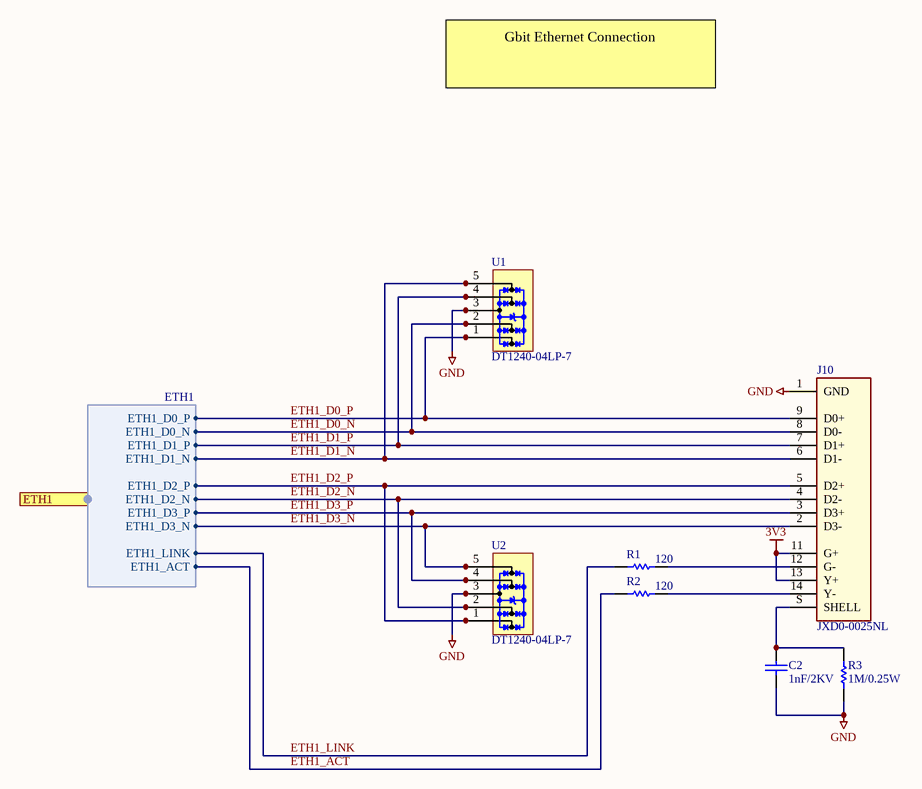
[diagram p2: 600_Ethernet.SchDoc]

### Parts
C2  value 1nF/2KV  [C/1206]  (hidden comment: 0567-Cap-1206-1nF/2KV)
J10  JXD0-0025NL  [PULSE_JXD0-0025NL]
R1  value 120  [R0402_RESC1005L]  (hidden comment: 1552-Res-0402-120)
R2  value 120  [R0402_RESC1005L]  (hidden comment: 1552-Res-0402-120)
R3  value 1M/0.25W  [R/1206]  (hidden comment: 1860-Res-1206-1M-5%-0.25W)
U1  DT1240-04LP-7  [10-UFDFN]
U2  DT1240-04LP-7  [10-UFDFN]

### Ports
ETH1 (harness ETH1)

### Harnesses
ETH1: ETH1_D0_P, ETH1_D0_N, ETH1_D1_N, ETH1_D1_P, ETH1_LINK, ETH1_ACT, ETH1_D2_P, ETH1_D2_N, ETH1_D3_N, ETH1_D3_P

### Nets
3V3: J10.11(G+) J10.13(Y+)
GND: C2.1 J10.1(GND) R3.2 U1.3(GND) U1.8(GND) U2.3(GND) U2.8(GND)
ETH1_ACT: R2.2 ; port ETH1.ETH1_ACT
ETH1_D0_N: J10.8(D0-) U1.2(IO2) U1.9(NC) ; port ETH1.ETH1_D0_N
ETH1_D0_P: J10.9(D0+) U1.1(IO1) U1.10(NC) ; port ETH1.ETH1_D0_P
ETH1_D1_N: J10.6(D1-) U1.5(IO4) U1.6(NC) ; port ETH1.ETH1_D1_N
ETH1_D1_P: J10.7(D1+) U1.4(IO3) U1.7(NC) ; port ETH1.ETH1_D1_P
ETH1_D2_N: J10.4(D2-) U2.2(IO2) U2.9(NC) ; port ETH1.ETH1_D2_N
ETH1_D2_P: J10.5(D2+) U2.1(IO1) U2.10(NC) ; port ETH1.ETH1_D2_P
ETH1_D3_N: J10.2(D3-) U2.5(IO4) U2.6(NC) ; port ETH1.ETH1_D3_N
ETH1_D3_P: J10.3(D3+) U2.4(IO3) U2.7(NC) ; port ETH1.ETH1_D3_P
ETH1_LINK: R1.2 ; port ETH1.ETH1_LINK
NetC2_2: C2.2 J10.S(SHELL) R3.1
NetJ10_12: J10.12(G-) R1.1
NetJ10_14: J10.14(Y-) R2.1

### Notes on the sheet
- Gbit Ethernet Connection

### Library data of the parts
C2 = 0567-Cap-1206-1nF/2KV: as C102 on sheet 100_Power
J10 = 1380-Conn-RJ45-GBe: (-40 to 85 DegC) CONN MAGJACK 1PORT 1000 BASE-T Isolated Taps; Mfr: Pulse; PN: 1380
R1 R2 = 1552-Res-0402-120: (-55 to 155 DegC AEC) RES 120 OHM 1% 1/16W 100ppm 0402; MfrNo: RMCF0402FT120R; Mfr: Stackpole Electronics; PN: 1552; Alt: AC0402FR-07120RL,CRGCQ0402F120R
R3 = 1860-Res-1206-1M-5%-0.25W: as R55 on sheet 100_Power
U1 U2 = 1657-DT1240-04LP-7: (-55 to 85 DegC) IC TVS DIODE 4ch Vrm:5.5V Vcl:11V@5.5A 10-UFDFN 0.5mm; Mfr: Diodes; PN: 1657

## Sheet 400_USB1_OTG.SchDoc: Ivy - Verdin Industrial Board Rev 1.1
size Letter; Organization: Toradex Solutions Inc.; Address1: 6415 Northwest Drive; Address2: Mississauga, ON, L4V 1X1; Address3: Canada
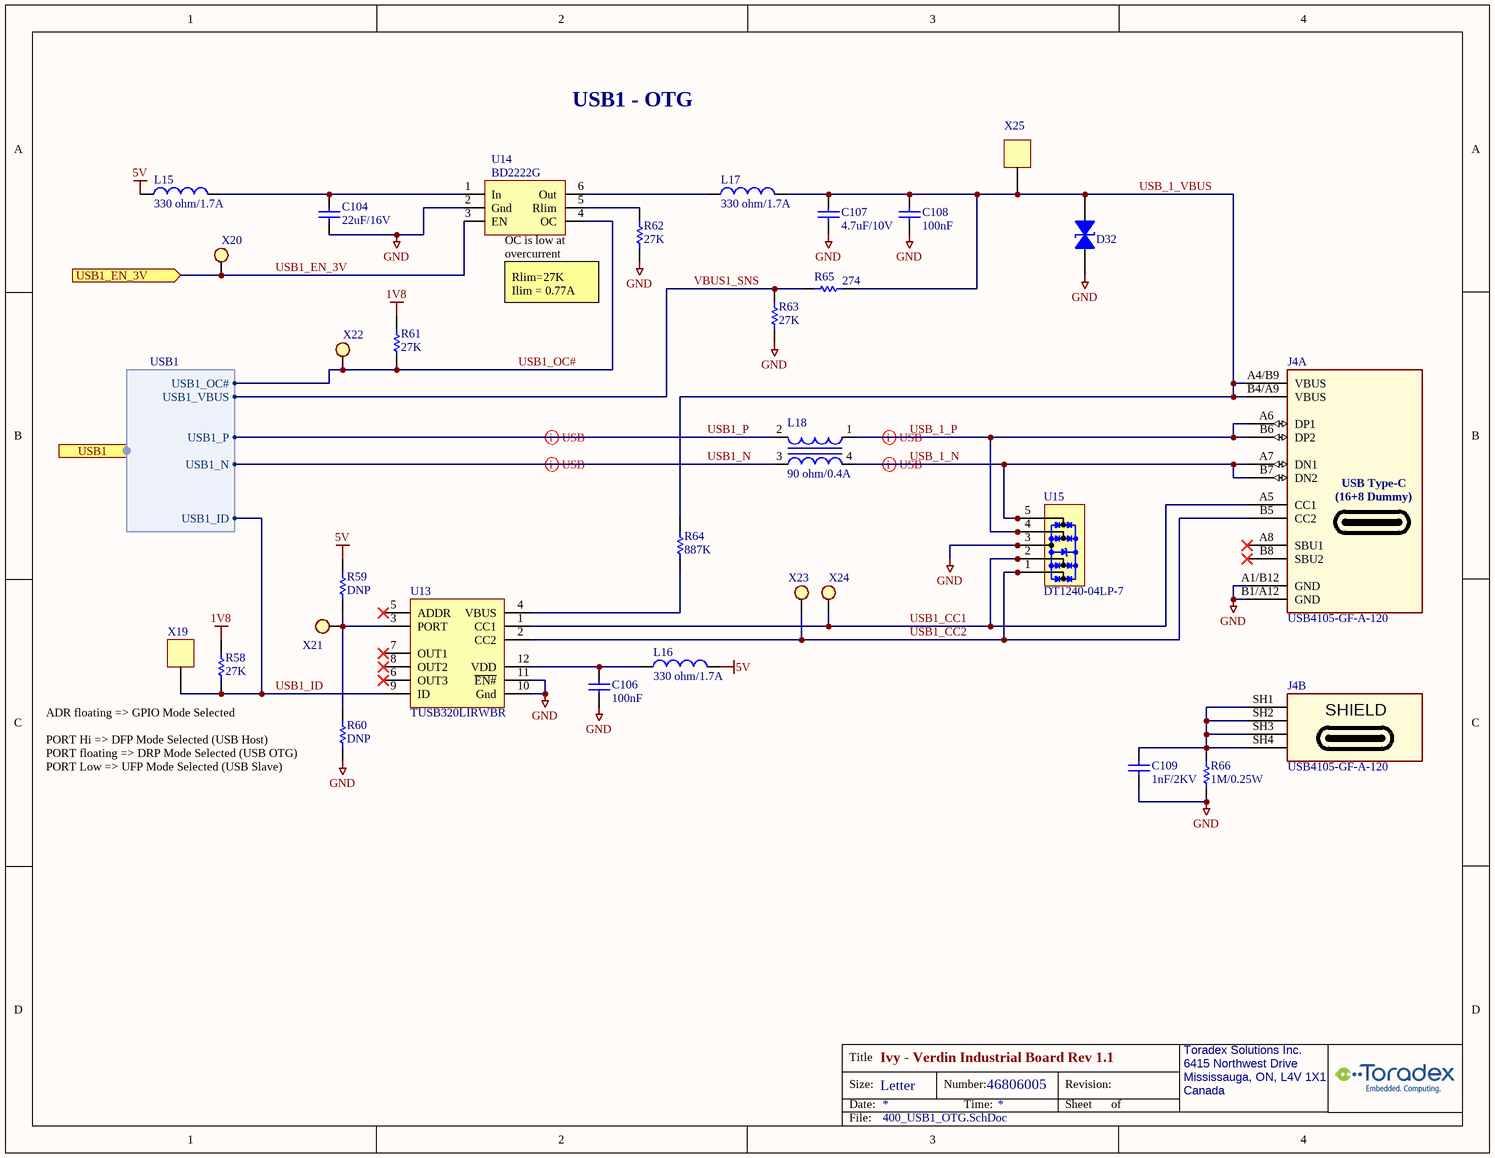
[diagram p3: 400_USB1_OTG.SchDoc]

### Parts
C104  value 22uF/16V  [C/0805]  (hidden comment: 1314-Cap-0805-22uF/16V)
C106  100nF  [C0402_CAPC1005L]
C107  value 4.7uF/10V  [C/0603]  (hidden comment: 2093-Cap-0603-4.7uF/10V)
C108  100nF  [C0402_CAPC1005L]
C109  value 1nF/2KV  [C/1206]  (hidden comment: 0567-Cap-1206-1nF/2KV)
D32  D5V0L1B2S9-7  [SOD923_DIO]  (value not drawn)
J4  USB4105-GF-A-120  [GCT_USB4105GFA120]  (parts A,B of 2)
L15  value 330 ohm/1.7A  [INDC1608x095]  (hidden comment: 0405-Fer-0603-330ohm/1.7A)
L16  value 330 ohm/1.7A  [INDC1608x095]  (hidden comment: 0405-Fer-0603-330ohm/1.7A)
L17  value 330 ohm/1.7A  [INDC1608x095]  (hidden comment: 0405-Fer-0603-330ohm/1.7A)
L18  90 ohm/0.4A  [COMMON_CHOKE_BOURNS_SRF2012-900YA]
R58  value 27K  [R0402_RESC1005L]  (hidden comment: 1538-Res-0402-27k)
R59  value DNP  [R/0603]  (hidden comment: 0000-Res-0603-DNP)
R60  value DNP  [R/0603]  (hidden comment: 0000-Res-0603-DNP)
R61  value 27K  [R0402_RESC1005L]  (hidden comment: 1538-Res-0402-27k)
R62  value 27K  [R0402_RESC1005L]  (hidden comment: 1538-Res-0402-27k)
R63  value 27K  [R0402_RESC1005L]  (hidden comment: 1538-Res-0402-27k)
R64  value 887K  [R0402_RESC1005L]  (hidden comment: 1809-Res-0402-887K)
R65  value 274  [R/0603]  (hidden comment: 0728-Res-0603-274ohm)
R66  value 1M/0.25W  [R/1206]  (hidden comment: 1860-Res-1206-1M-5%-0.25W)
U13  TUSB320LIRWBR  [QFN40P160X160X40-12N]
U14  BD2222G  [sot23-6]
U15  DT1240-04LP-7  [10-UFDFN]
X19  000-TestPoint  [TestPoint_1]  (value not drawn)
X20  000-TestPoint2  [TestPoint_3]  (value not drawn)
X21  000-TestPoint2  [TestPoint_3]  (value not drawn)
X22  000-TestPoint2  [TestPoint_3]  (value not drawn)
X23  000-TestPoint2  [TestPoint_3]  (value not drawn)
X24  000-TestPoint2  [TestPoint_3]  (value not drawn)
X25  000-TestPoint  [TestPoint_1]  (value not drawn)

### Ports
USB1 (harness USB1), USB1_EN_3V (in)

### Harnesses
USB1: USB1_N, USB1_P, USB1_ID, USB1_VBUS, USB1_OC#

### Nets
1V8: R58.2 R61.2
5V: L15.1 L16.1 R59.2
GND: C104.1 C106.1 C107.1 C108.1 C109.1 D32.2 J4.A1/B12(GND) J4.B1/A12(GND) R60.1 R62.1 R63.1 R66.2 U13.10(Gnd) U13.11(~{EN#}) U14.2(Gnd) U15.3(GND) U15.8(GND)
USB1_CC1: J4.A5(CC1) U13.1(CC1) U15.2(IO2) U15.9(NC) X24.1
USB1_CC2: J4.B5(CC2) U13.2(CC2) U15.1(IO1) U15.10(NC) X23.1
USB1_EN_3V: U14.3(EN) X20.1 ; port USB1_EN_3V
USB1_ID: R58.1 U13.9(ID) X19.1 ; port USB1.USB1_ID
USB1_N: L18.3 ; port USB1.USB1_N
USB1_OC#: R61.1 U14.4(OC) X22.1 ; port USB1.USB1_OC#
USB1_P: L18.2 ; port USB1.USB1_P
USB_1_N: J4.A7(DN1) J4.B7(DN2) L18.4 U15.5(IO4) U15.6(NC)
USB_1_P: J4.A6(DP1) J4.B6(DP2) L18.1 U15.4(IO3) U15.7(NC)
USB_1_VBUS: C107.2 C108.2 D32.1 J4.A4/B9(VBUS) J4.B4/A9(VBUS) L17.2 R64.1 R65.1 X25.1
VBUS1_SNS: R63.2 R65.2 ; port USB1.USB1_VBUS  [project net USB1_VBUS]
NetC104_2: C104.2 L15.2 U14.1(In)
NetC106_2: C106.2 L16.2 U13.12(VDD)
NetC109_2: C109.2 J4.SH1(SHIELD) J4.SH2(SHIELD) J4.SH3(SHIELD) J4.SH4(SHIELD) R66.1
NetL17_1: L17.1 U14.6(Out)
NetR59_1: R59.1 R60.2 U13.3(PORT) X21.1
NetR62_2: R62.2 U14.5(Rlim)
NetR64_2: R64.2 U13.4(VBUS)

Not connected (* = marked no-connect by the designer): J4 A8(SBU1)* B8(SBU2)*; U13 5(ADDR)* 6(OUT3)* 7(OUT1)* 8(OUT2)*

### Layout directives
differential pair; differential pair class USB: USB1_N, USB1_P, USB_1_N, USB_1_P

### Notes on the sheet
- USB1 - OTG
- (near U14) OC is low at
- (near U14) overcurrent
- Rlim=27K
  Ilim = 0.77A
- ADR floating => GPIO Mode Selected
- PORT Hi => DFP Mode Selected (USB Host)
- (near R60) PORT floating => DRP Mode Selected (USB OTG)
- (near R60) PORT Low => UFP Mode Selected (USB Slave)

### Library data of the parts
C104 = 1314-Cap-0805-22uF/16V: (-55 to 85 DegC) CAP CER 22uF 16V X5R 0805; Mfr: Samsung; MfrNo: CL21A226MOQNNNE; PN: 1314; Alt: CL21A226MOCLRNC,CL21A226KOQNNNG,GRM21BR61C226ME44L,EMK212BBJ226MG-T
C106 C108 = 1566-Cap-0402-100nF/50V: as C82 on sheet 100_Power
C107 = 2093-Cap-0603-4.7uF/10V: (-55 to 85 DegC) CAP CER 4.7UF 10V 20% X5R 0603; MfrNo: CL10A475KP8NNNC; Mfr: Samsung; PN: 2093
C109 = 0567-Cap-1206-1nF/2KV: as C102 on sheet 100_Power
D32 = 1655-D5V0L1B2S9-7: (-65 to 155 DegC) TVS DIODE Vwm:5V Vcl:14V@6A SOD-923; Mfr: Diodes; PN: 1655
J4 = 1660-Conn-USB-Type-C: (-40 to 85 DegC) Conn USB TYPE C RA, 24 (16+8 Dummy) Position, SMT/TH; Mfr: Global Connector Technology; Desc: (-40 to 85 DegC) Conn USB TYPE C RA SMT/TH; PN: 1660
L15-L17 = 0405-Fer-0603-330ohm/1.7A: (-55 to 125 DegC) FERRITE BEAD 330 OHM 0603 1.7A 80mohm, typ 48mohm; Mfr: TDK Corporation; MfrNo: MPZ1608S331ATA00; PN: 405; TR: 445-5221-2-ND; DR: 445-5221-6-ND; DR2: 810-MPZ1608S331ATA00
L18 = 0277-Ind-2x1.2-90ohm/0.4A-Choke: INDUCTOR COMMON MODE 90 OHM 0.4A 0.3ohm; MfrNo: SRF2012-900YA; Mfr: Bourns Inc.; PN: 277; Alt: 445-2207-1-ND
R58 R61-R63 = 1538-Res-0402-27k: as R36 on sheet 100_Power
R59 R60 = 0000-Res-0603-DNP: RES 0603
R64 = 1809-Res-0402-887K: (-55 to 155 DegC AEC) RES 887K OHM 1% 1/16W 100ppm 0402; MfrNo: RMCF0402FT887K; Mfr: Stackpole Electronics; PN: 1809
R65 = 0728-Res-0603-274ohm: RES SMD 274 OHM 1% 1/10W 0603; MfrNo: RC0603FR-07274RL; Mfr: Yageo; PN: 728; TR: 311-274HRTR-ND
R66 = 1860-Res-1206-1M-5%-0.25W: as R55 on sheet 100_Power
U13 = 1458-TUSB320LI: (-40 to 85 DegC) IC USB TYPE-C CC LOGIC AND PORT Control 12-X2QFN; Mfr: Texas Instruments; PN: 1458
U14 = 1469-BD2222G: (-40 to 85 DegC) IC PWR SWITCH 2.8-5.5V EN-Active-High ENth:2.0V No-Discharge 89mohm typ ADJ 0.2-1.7A 6SSOP; Mfr: Rohm; MfrNo: BD2222G-GTR; PN: 1469; Note: Similar BD2242G, TPS25221, TPS2553, AP22653, RT9728A, RT9728B, RT9728C, AP2553, MIC2009YM6, MIC2019YM6, MIC2009A-1YM6,MIC2019A-1YM6
U15 = 1657-DT1240-04LP-7: as U1 on sheet 600_Ethernet
X19 X25 = 000-TestPoint: as X1 on sheet 100_Power
X20-X24 = 000-TestPoint2: TestPoint SMD; Note: PCB footprint only, no parts to buy or assemble

## Sheet 220_Verdin_Full.SchDoc: Ivy - Verdin Industrial Board Rev 1.1
size A3; Organization: Toradex Solutions Inc.; Address1: 6415 Northwest Drive; Address2: Mississauga, ON, L4V 1X1; Address3: Canada
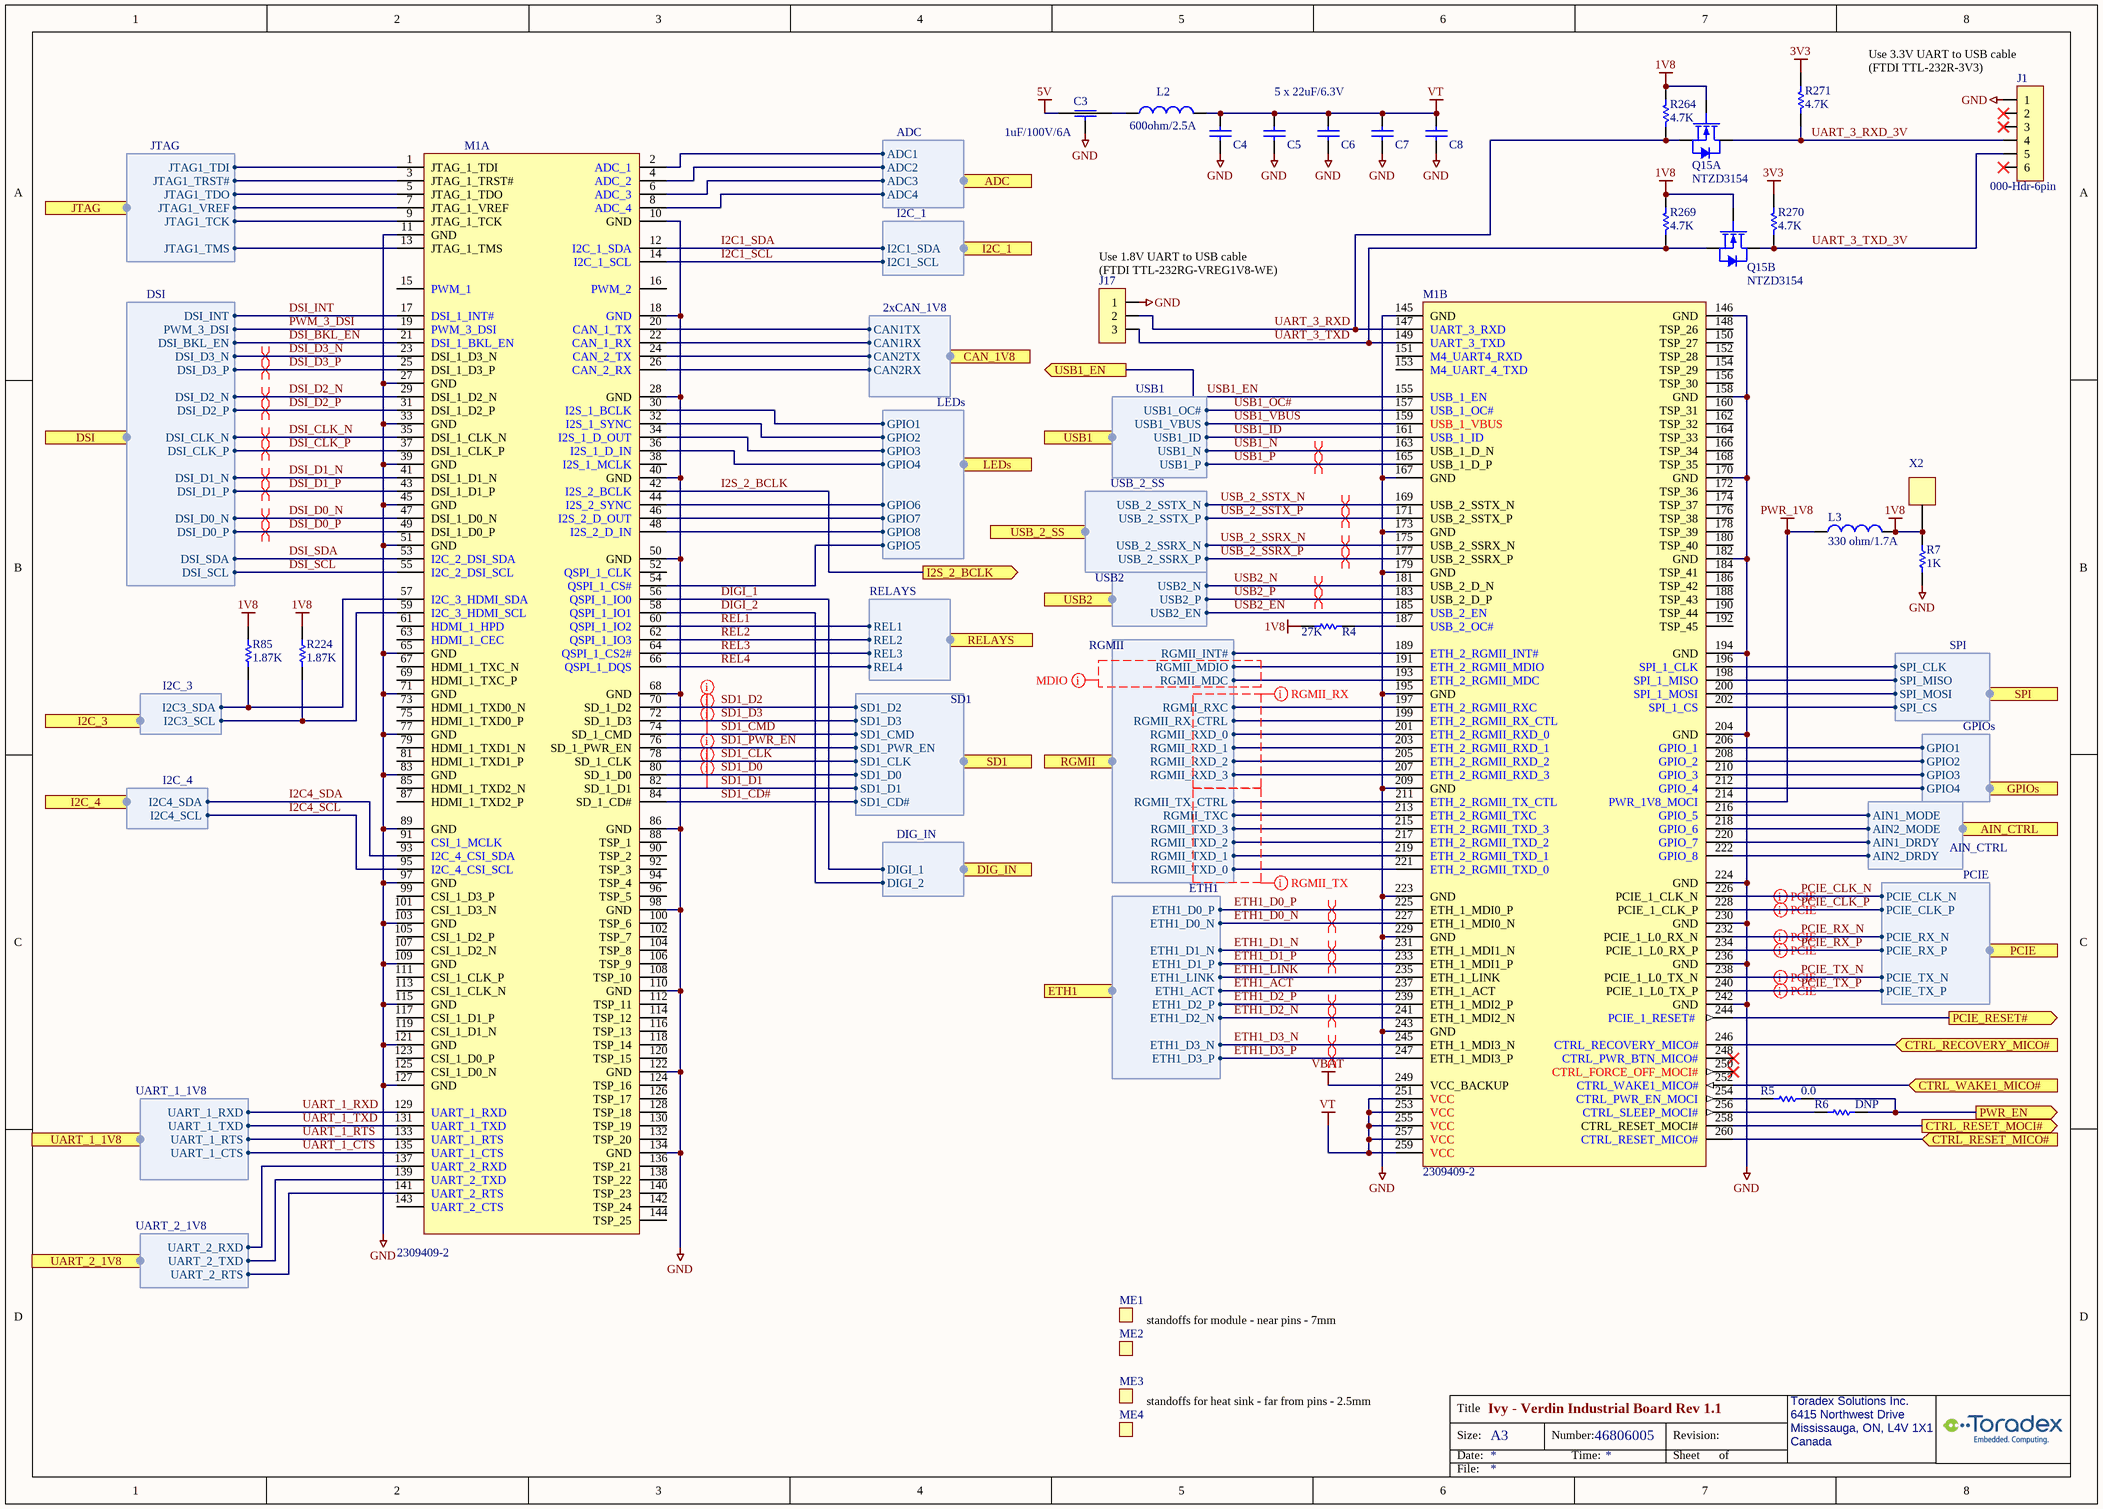
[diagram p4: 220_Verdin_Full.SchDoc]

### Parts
C3  value 1uF/100V/6A  [C/1206_3P]  (hidden comment: 0753-Cap 3P-1206-1uF/100V/6A)
C4  22uF/6.3V  [C0402_CAPC1005L]  (value not drawn)
C5  22uF/6.3V  [C0402_CAPC1005L]  (value not drawn)
C6  22uF/6.3V  [C0402_CAPC1005L]  (value not drawn)
C7  22uF/6.3V  [C0402_CAPC1005L]  (value not drawn)
C8  22uF/6.3V  [C0402_CAPC1005L]  (value not drawn)
J1  000-Hdr-6pin  [HDR1X6]
J17  000-Hdr-3pin  [HDR1X3]  (value not drawn)
L2  value 600ohm/2.5A  [INDP1206]  (hidden comment: 1641-Fer-1206-600ohm/2.5A)
L3  value 330 ohm/1.7A  [INDC1608x095]  (hidden comment: 0405-Fer-0603-330ohm/1.7A)
M1  2309409-2  [CON-TE-2309409-2_TORADEX_VERDIN_MTG_rev2]  (parts A,B of 2)
ME1  9774070243R  [MTG_POST WURTH 774070243]  (value not drawn)
ME2  9774070243R  [MTG_POST WURTH 774070243]  (value not drawn)
ME3  9774025243R  [WURTH_9774025243R]  (value not drawn)
ME4  9774025243R  [WURTH_9774025243R]  (value not drawn)
Q15  NTZD3154  [SOT563]  (parts A,B of 2)
R4  value 27K  [R0402_RESC1005L]  (hidden comment: 1538-Res-0402-27k)
R5  value 0.0  [R/0603]  (hidden comment: 0195-Res-0603-0.0ohm)
R6  value DNP  [R/0603]  (hidden comment: 0000-Res-0603-DNP)
R7  value 1K  [R0402_RESC1005L]  (hidden comment: 1650-Res-0402-1K)
R85  value 1.87K  [R0402_RESC1005L]  (hidden comment: 1536-Res-0402-1.87K)
R224  value 1.87K  [R0402_RESC1005L]  (hidden comment: 1536-Res-0402-1.87K)
R264  value 4.7K  [R0402_RESC1005L]  (hidden comment: 2233-Res-0402-4.7K)
R269  value 4.7K  [R0402_RESC1005L]  (hidden comment: 2233-Res-0402-4.7K)
R270  value 4.7K  [R0402_RESC1005L]  (hidden comment: 2233-Res-0402-4.7K)
R271  value 4.7K  [R0402_RESC1005L]  (hidden comment: 2233-Res-0402-4.7K)
X2  000-TestPoint  [TestPoint_1]  (value not drawn)

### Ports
ADC (harness ADC), AIN_CTRL (harness AIN_CTRL), CAN_1V8 (harness 2xCAN_1V8), CTRL_RECOVERY_MICO# (in), CTRL_RESET_MICO# (in), CTRL_RESET_MOCI# (out), CTRL_WAKE1_MICO# (in), DIG_IN (harness DIG_IN), DSI (harness DSI), ETH1 (harness ETH1), GPIOs (harness GPIOs), I2C_1 (harness I2C_1), I2C_3 (harness I2C_3), I2C_4 (harness I2C_4), I2S_2_BCLK (out), JTAG (harness JTAG), LEDs (harness LEDs), PCIE (harness PCIe), PCIE_RESET# (out), PWR_EN (out), RELAYS (harness RELAYS), RGMII (harness RGMII), SD1 (harness SD1), SPI (harness SPI), UART_1_1V8 (harness UART_1_1V8), UART_2_1V8 (harness UART_2_1V8), USB1 (harness USB1), USB1_EN (out), USB2 (harness USB2), USB_2_SS (harness USB_2_SS)

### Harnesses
ETH1: ETH1_D0_P, ETH1_D0_N, ETH1_D1_N, ETH1_D1_P, ETH1_LINK, ETH1_ACT, ETH1_D2_P, ETH1_D2_N, ETH1_D3_N, ETH1_D3_P
USB2: USB2_N, USB2_P, USB2_EN
USB1: USB1_N, USB1_P, USB1_ID, USB1_VBUS, USB1_OC#
PCIE: PCIE_CLK_N, PCIE_CLK_P, PCIE_RX_N, PCIE_RX_P, PCIE_TX_N, PCIE_TX_P
SPI: SPI_CLK, SPI_MISO, SPI_MOSI, SPI_CS
AIN_CTRL: AIN1_MODE, AIN2_MODE, AIN1_DRDY, AIN2_DRDY
GPIOs: GPIO1, GPIO2, GPIO3, GPIO4
RGMII: RGMII_TXD_0, RGMII_TXD_1, RGMII_TXD_2, RGMII_TXD_3, RGMII_TXC, RGMII_TX_CTRL, RGMII_RXD_0, RGMII_RXD_1, RGMII_RXD_2, RGMII_RXD_3, RGMII_RXC, RGMII_RX_CTRL, RGMII_MDIO, RGMII_MDC, RGMII_INT#
SD1: SD1_D2, SD1_D3, SD1_CMD, SD1_PWR_EN, SD1_CLK, SD1_D0, SD1_D1, SD1_CD#
2xCAN_1V8: CAN1TX, CAN1RX, CAN2TX, CAN2RX
UART_1_1V8: UART_1_RXD, UART_1_TXD, UART_1_RTS, UART_1_CTS
UART_2_1V8: UART_2_RXD, UART_2_TXD, UART_2_RTS
RELAYS: REL1, REL2, REL3, REL4
I2C_1: I2C1_SDA, I2C1_SCL
DIG_IN: DIGI_1, DIGI_2
JTAG: JTAG1_TDI, JTAG1_TRST#, JTAG1_TDO, JTAG1_VREF, JTAG1_TCK, JTAG1_TMS
LEDs: GPIO1, GPIO2, GPIO3, GPIO4, GPIO7, GPIO8, GPIO6, GPIO5
I2C_4: I2C4_SDA, I2C4_SCL
DSI: DSI_SDA, DSI_SCL, DSI_BKL_EN, PWM_3_DSI, DSI_INT, DSI_D3_N, DSI_D3_P, DSI_D2_N, DSI_D2_P, DSI_CLK_N, DSI_CLK_P, DSI_D1_N, DSI_D1_P, DSI_D0_N, DSI_D0_P
ADC: ADC1, ADC2, ADC3, ADC4
I2C_3: I2C3_SDA, I2C3_SCL
USB_2_SS: USB_2_SSTX_N, USB_2_SSTX_P, USB_2_SSRX_N, USB_2_SSRX_P

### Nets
1V8: L3.1 Q15.2(G) Q15.5(G) R4.1 R7.2 R85.2 R224.2 R264.1 R269.1 X2.1
3V3: R270.1 R271.1
5V: C3.1(In/Out)
GND: C3.2(Gnd) C4.1 C5.1 C6.1 C7.1 C8.1 J1.1 J17.1 M1.10(GND) M1.11(GND) M1.18(GND) M1.27(GND) M1.28(GND) M1.33(GND) M1.39(GND) M1.40(GND) M1.45(GND) M1.50(GND) M1.51(GND) M1.65(GND) M1.68(GND) M1.71(GND) M1.77(GND) M1.83(GND) M1.86(GND) M1.89(GND) M1.97(GND) M1.98(GND) M1.103(GND) M1.109(GND) M1.110(GND) M1.115(GND) M1.121(GND) M1.122(GND) M1.127(GND) M1.134(GND) M1.145(GND) M1.146(GND) M1.158(GND) M1.167(GND) M1.170(GND) M1.173(GND) M1.179(GND) M1.182(GND) M1.194(GND) M1.195(GND) M1.204(GND) M1.209(GND) M1.223(GND) M1.224(GND) M1.229(GND) M1.230(GND) M1.236(GND) M1.242(GND) M1.243(GND) R7.1
PWR_1V8: L3.2 M1.214(PWR_1V8_MOCI)
VBAT: M1.249(VCC_BACKUP)
VT: C4.2 C5.2 C6.2 C7.2 C8.2 L2.2 M1.251(VCC) M1.253(VCC) M1.255(VCC) M1.257(VCC) M1.259(VCC)
CAN1RX_1V8: M1.22(CAN_1_RX) ; port CAN_1V8.CAN1RX
CAN1TX_1V8: M1.20(CAN_1_TX) ; port CAN_1V8.CAN1TX
CAN2RX_1V8: M1.26(CAN_2_RX) ; port CAN_1V8.CAN2RX
CAN2TX_1V8: M1.24(CAN_2_TX) ; port CAN_1V8.CAN2TX
CTRL_RECOVERY_MICO#: M1.246(CTRL_RECOVERY_MICO#) ; port CTRL_RECOVERY_MICO#
CTRL_RESET_MICO#: M1.260(CTRL_RESET_MICO#) ; port CTRL_RESET_MICO#
CTRL_RESET_MOCI#: M1.258(CTRL_RESET_MOCI#) ; port CTRL_RESET_MOCI#
CTRL_WAKE1_MICO#: M1.252(CTRL_WAKE1_MICO#) ; port CTRL_WAKE1_MICO#
DIGI_1: M1.56(QSPI_1_IO0) ; port DIG_IN.DIGI_1
DIGI_2: M1.58(QSPI_1_IO1) ; port DIG_IN.DIGI_2
DSI_BKL_EN: M1.21(DSI_1_BKL_EN) ; port DSI.DSI_BKL_EN
DSI_CLK_N: M1.35(DSI_1_CLK_N) ; port DSI.DSI_CLK_N  [project net DSI_1_CLK_N]
DSI_CLK_P: M1.37(DSI_1_CLK_P) ; port DSI.DSI_CLK_P  [project net DSI_1_CLK_P]
DSI_D0_N: M1.47(DSI_1_D0_N) ; port DSI.DSI_D0_N  [project net DSI_1_D0_N]
DSI_D0_P: M1.49(DSI_1_D0_P) ; port DSI.DSI_D0_P  [project net DSI_1_D0_P]
DSI_D1_N: M1.41(DSI_1_D1_N) ; port DSI.DSI_D1_N  [project net DSI_1_D1_N]
DSI_D1_P: M1.43(DSI_1_D1_P) ; port DSI.DSI_D1_P  [project net DSI_1_D1_P]
DSI_D2_N: M1.29(DSI_1_D2_N) ; port DSI.DSI_D2_N  [project net DSI_1_D2_N]
DSI_D2_P: M1.31(DSI_1_D2_P) ; port DSI.DSI_D2_P  [project net DSI_1_D2_P]
DSI_D3_N: M1.23(DSI_1_D3_N) ; port DSI.DSI_D3_N  [project net DSI_1_D3_N]
DSI_D3_P: M1.25(DSI_1_D3_P) ; port DSI.DSI_D3_P  [project net DSI_1_D3_P]
DSI_INT: M1.17(DSI_1_INT#) ; port DSI.DSI_INT
DSI_SCL: M1.55(I2C_2_DSI_SCL) ; port DSI.DSI_SCL
DSI_SDA: M1.53(I2C_2_DSI_SDA) ; port DSI.DSI_SDA
ETH1_ACT: M1.237(ETH_1_ACT) ; port ETH1.ETH1_ACT
ETH1_D0_N: M1.227(ETH_1_MDI0_N) ; port ETH1.ETH1_D0_N
ETH1_D0_P: M1.225(ETH_1_MDI0_P) ; port ETH1.ETH1_D0_P
ETH1_D1_N: M1.231(ETH_1_MDI1_N) ; port ETH1.ETH1_D1_N
ETH1_D1_P: M1.233(ETH_1_MDI1_P) ; port ETH1.ETH1_D1_P
ETH1_D2_N: M1.241(ETH_1_MDI2_N) ; port ETH1.ETH1_D2_N
ETH1_D2_P: M1.239(ETH_1_MDI2_P) ; port ETH1.ETH1_D2_P
ETH1_D3_N: M1.245(ETH_1_MDI3_N) ; port ETH1.ETH1_D3_N
ETH1_D3_P: M1.247(ETH_1_MDI3_P) ; port ETH1.ETH1_D3_P
ETH1_LINK: M1.235(ETH_1_LINK) ; port ETH1.ETH1_LINK
GPIO1: M1.206(GPIO_1) ; port GPIOs.GPIO1
I2C1_SCL: M1.14(I2C_1_SCL) ; port I2C_1.I2C1_SCL
I2C1_SDA: M1.12(I2C_1_SDA) ; port I2C_1.I2C1_SDA
I2C4_SCL: M1.95(I2C_4_CSI_SCL) ; port I2C_4.I2C4_SCL
I2C4_SDA: M1.93(I2C_4_CSI_SDA) ; port I2C_4.I2C4_SDA
I2S_2_BCLK: M1.42(I2S_2_BCLK) ; port I2S_2_BCLK
JTAG1_TCK: M1.9(JTAG_1_TCK) ; port JTAG.JTAG1_TCK
JTAG1_TDI: M1.1(JTAG_1_TDI) ; port JTAG.JTAG1_TDI
JTAG1_TDO: M1.5(JTAG_1_TDO) ; port JTAG.JTAG1_TDO
JTAG1_TMS: M1.13(JTAG_1_TMS) ; port JTAG.JTAG1_TMS
JTAG1_TRST#: M1.3(JTAG_1_TRST#) ; port JTAG.JTAG1_TRST#
PCIE_CLK_N: M1.226(PCIE_1_CLK_N) ; port PCIE.PCIE_CLK_N
PCIE_CLK_P: M1.228(PCIE_1_CLK_P) ; port PCIE.PCIE_CLK_P
PCIE_RESET#: M1.244(PCIE_1_RESET#) ; port PCIE_RESET#
PCIE_RX_N: M1.232(PCIE_1_L0_RX_N) ; port PCIE.PCIE_RX_N
PCIE_RX_P: M1.234(PCIE_1_L0_RX_P) ; port PCIE.PCIE_RX_P
PCIE_TX_N: M1.238(PCIE_1_L0_TX_N) ; port PCIE.PCIE_TX_N
PCIE_TX_P: M1.240(PCIE_1_L0_TX_P) ; port PCIE.PCIE_TX_P
PWM_3_DSI: M1.19(PWM_3_DSI) ; port DSI.PWM_3_DSI
PWR_EN: R5.1 R6.1 ; port PWR_EN
REL1: M1.60(QSPI_1_IO2) ; port RELAYS.REL1
REL2: M1.62(QSPI_1_IO3) ; port RELAYS.REL2
REL3: M1.64(QSPI_1_CS2#) ; port RELAYS.REL3
REL4: M1.66(QSPI_1_DQS) ; port RELAYS.REL4
SD1_CD#: M1.84(SD_1_CD#) ; port SD1.SD1_CD#
SD1_CLK: M1.78(SD_1_CLK) ; port SD1.SD1_CLK
SD1_CMD: M1.74(SD_1_CMD) ; port SD1.SD1_CMD
SD1_D0: M1.80(SD_1_D0) ; port SD1.SD1_D0
SD1_D1: M1.82(SD_1_D1) ; port SD1.SD1_D1
SD1_D2: M1.70(SD_1_D2) ; port SD1.SD1_D2
SD1_D3: M1.72(SD_1_D3) ; port SD1.SD1_D3
SD1_PWR_EN: M1.76(SD_1_PWR_EN) ; port SD1.SD1_PWR_EN
SPI_CLK: M1.196(SPI_1_CLK) ; port SPI.SPI_CLK
SPI_CS: M1.202(SPI_1_CS) ; port SPI.SPI_CS
SPI_MISO: M1.198(SPI_1_MISO) ; port SPI.SPI_MISO
SPI_MOSI: M1.200(SPI_1_MOSI) ; port SPI.SPI_MOSI
UART_1_CTS: M1.135(UART_1_CTS) ; port UART_1_1V8.UART_1_CTS
UART_1_RTS: M1.133(UART_1_RTS) ; port UART_1_1V8.UART_1_RTS
UART_1_RXD: M1.129(UART_1_RXD) ; port UART_1_1V8.UART_1_RXD
UART_1_TXD: M1.131(UART_1_TXD) ; port UART_1_1V8.UART_1_TXD
UART_2_RTS: M1.141(UART_2_RTS) ; port UART_2_1V8.UART_2_RTS
UART_2_RXD: M1.137(UART_2_RXD) ; port UART_2_1V8.UART_2_RXD
UART_2_TXD: M1.139(UART_2_TXD) ; port UART_2_1V8.UART_2_TXD
UART_3_RXD: J17.2 M1.147(UART_3_RXD) Q15.1(S) R264.2
UART_3_RXD_3V: J1.4 Q15.6(D) R271.2
UART_3_TXD: J17.3 M1.149(UART_3_TXD) Q15.4(S) R269.2
UART_3_TXD_3V: J1.5 Q15.3(D) R270.2
USB1_EN: M1.155(USB_1_EN) ; port USB1_EN
USB1_ID: M1.161(USB_1_ID) ; port USB1.USB1_ID
USB1_N: M1.163(USB_1_D_N) ; port USB1.USB1_N
USB1_OC#: M1.157(USB_1_OC#) ; port USB1.USB1_OC#
USB1_P: M1.165(USB_1_D_P) ; port USB1.USB1_P
USB1_VBUS: M1.159(USB_1_VBUS) ; port USB1.USB1_VBUS
USB2_EN: M1.185(USB_2_EN) ; port USB2.USB2_EN
USB2_N: M1.181(USB_2_D_N) ; port USB2.USB2_N
USB2_P: M1.183(USB_2_D_P) ; port USB2.USB2_P
USB_2_SSRX_N: M1.175(USB_2_SSRX_N) ; port USB_2_SS.USB_2_SSRX_N
USB_2_SSRX_P: M1.177(USB_2_SSRX_P) ; port USB_2_SS.USB_2_SSRX_P
USB_2_SSTX_N: M1.169(USB_2_SSTX_N) ; port USB_2_SS.USB_2_SSTX_N
USB_2_SSTX_P: M1.171(USB_2_SSTX_P) ; port USB_2_SS.USB_2_SSTX_P
NetC3_3: C3.3(In/Out) L2.1
NetC97_1: M1.2(ADC_1) ; port ADC.ADC1
NetC100_1: M1.4(ADC_2) ; port ADC.ADC2
NetC101_1: M1.6(ADC_3) ; port ADC.ADC3
NetC103_1: M1.8(ADC_4) ; port ADC.ADC4
NetJ2_8: M1.208(GPIO_2) ; port GPIOs.GPIO2
NetJ2_10: M1.210(GPIO_3) ; port GPIOs.GPIO3
NetJ13_1: M1.7(JTAG_1_VREF) ; port JTAG.JTAG1_VREF
NetM1_30: M1.30(I2S_1_BCLK) ; port LEDs.GPIO1
NetM1_32: M1.32(I2S_1_SYNC) ; port LEDs.GPIO2
NetM1_34: M1.34(I2S_1_D_OUT) ; port LEDs.GPIO3
NetM1_36: M1.36(I2S_1_D_IN) ; port LEDs.GPIO4
NetM1_44: M1.44(I2S_2_SYNC) ; port LEDs.GPIO6
NetM1_46: M1.46(I2S_2_D_OUT) ; port LEDs.GPIO7
NetM1_48: M1.48(I2S_2_D_IN) ; port LEDs.GPIO8
NetM1_54: M1.54(QSPI_1_CS#) ; port LEDs.GPIO5
NetM1_57: M1.57(I2C_3_HDMI_SDA) R85.1 ; port I2C_3.I2C3_SDA
NetM1_59: M1.59(I2C_3_HDMI_SCL) R224.1 ; port I2C_3.I2C3_SCL
NetM1_187: M1.187(USB_2_OC#) R4.2
NetM1_189: M1.189(ETH_2_RGMII_INT#) ; port RGMII.RGMII_INT#
NetM1_191: M1.191(ETH_2_RGMII_MDIO) ; port RGMII.RGMII_MDIO
NetM1_193: M1.193(ETH_2_RGMII_MDC) ; port RGMII.RGMII_MDC
NetM1_197: M1.197(ETH_2_RGMII_RXC) ; port RGMII.RGMII_RXC
NetM1_199: M1.199(ETH_2_RGMII_RX_CTL) ; port RGMII.RGMII_RX_CTRL
NetM1_201: M1.201(ETH_2_RGMII_RXD_0) ; port RGMII.RGMII_RXD_0
NetM1_203: M1.203(ETH_2_RGMII_RXD_1) ; port RGMII.RGMII_RXD_1
NetM1_205: M1.205(ETH_2_RGMII_RXD_2) ; port RGMII.RGMII_RXD_2
NetM1_207: M1.207(ETH_2_RGMII_RXD_3) ; port RGMII.RGMII_RXD_3
NetM1_211: M1.211(ETH_2_RGMII_TX_CTL) ; port RGMII.RGMII_TX_CTRL
NetM1_212: M1.212(GPIO_4) ; port GPIOs.GPIO4
NetM1_213: M1.213(ETH_2_RGMII_TXC) ; port RGMII.RGMII_TXC
NetM1_215: M1.215(ETH_2_RGMII_TXD_3) ; port RGMII.RGMII_TXD_3
NetM1_216: M1.216(GPIO_5) ; port AIN_CTRL.AIN1_MODE
NetM1_217: M1.217(ETH_2_RGMII_TXD_2) ; port RGMII.RGMII_TXD_2
NetM1_218: M1.218(GPIO_6) ; port AIN_CTRL.AIN2_MODE
NetM1_219: M1.219(ETH_2_RGMII_TXD_1) ; port RGMII.RGMII_TXD_1
NetM1_220: M1.220(GPIO_7) ; port AIN_CTRL.AIN1_DRDY
NetM1_221: M1.221(ETH_2_RGMII_TXD_0) ; port RGMII.RGMII_TXD_0
NetM1_222: M1.222(GPIO_8) ; port AIN_CTRL.AIN2_DRDY
NetM1_254: M1.254(CTRL_PWR_EN_MOCI) R5.2
NetM1_256: M1.256(CTRL_SLEEP_MOCI#) R6.2

Not connected (* = marked no-connect by the designer): J1 2* 3* 6*; M1 15(PWM_1) 16(PWM_2) 38(I2S_1_MCLK) 52(QSPI_1_CLK) 61(HDMI_1_HPD) 63(HDMI_1_CEC) 67(HDMI_1_TXC_N) 69(HDMI_1_TXC_P) 73(HDMI_1_TXD0_N) 75(HDMI_1_TXD0_P) 79(HDMI_1_TXD1_N) 81(HDMI_1_TXD1_P) 85(HDMI_1_TXD2_N) 87(HDMI_1_TXD2_P) 88(TSP_1) 90(TSP_2) 91(CSI_1_MCLK) 92(TSP_3) 94(TSP_4) 96(TSP_5) 99(CSI_1_D3_P) 100(TSP_6) 101(CSI_1_D3_N) 102(TSP_7) 104(TSP_8) 105(CSI_1_D2_P) 106(TSP_9) 107(CSI_1_D2_N) 108(TSP_10) 111(CSI_1_CLK_P) 112(TSP_11) 113(CSI_1_CLK_N) 114(TSP_12) 116(TSP_13) 117(CSI_1_D1_P) 118(TSP_14) 119(CSI_1_D1_N) 120(TSP_15) 123(CSI_1_D0_P) 124(TSP_16) 125(CSI_1_D0_N) 126(TSP_17) 128(TSP_18) 130(TSP_19) 132(TSP_20) 136(TSP_21) 138(TSP_22) 140(TSP_23) 142(TSP_24) 143(UART_2_CTS) 144(TSP_25) 148(TSP_26) 150(TSP_27) 151(M4_UART4_RXD) 152(TSP_28) 153(M4_UART_4_TXD) 154(TSP_29) 156(TSP_30) 160(TSP_31) 162(TSP_32) 164(TSP_33) 166(TSP_34) 168(TSP_35) 172(TSP_36) 174(TSP_37) 176(TSP_38) 178(TSP_39) 180(TSP_40) 184(TSP_41) 186(TSP_42) 188(TSP_43) 190(TSP_44) 192(TSP_45) 248(CTRL_PWR_BTN_MICO#)* 250(CTRL_FORCE_OFF_MOCI#)*

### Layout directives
differential pair; differential pair class PCIE: PCIE_CLK_N, PCIE_CLK_P, PCIE_RX_N, PCIE_RX_P, PCIE_TX_N, PCIE_TX_P
differential pair; differential pair class ETH1: ETH1_D0_N, ETH1_D0_P, ETH1_D1_N, ETH1_D1_P, ETH1_D2_N, ETH1_D2_P, ETH1_D3_N, ETH1_D3_P
differential pair; differential pair class USB2; differential pair class USB: USB2_N, USB2_P
differential pair; differential pair class USB1; differential pair class USB: USB1_N, USB1_P
net class SD1: SD1_CLK, SD1_CMD, SD1_D0, SD1_D1, SD1_D2, SD1_D3
differential pair; differential pair class DSI: DSI_1_CLK_N, DSI_1_CLK_P, DSI_1_D0_N, DSI_1_D0_P, DSI_1_D1_N, DSI_1_D1_P, DSI_1_D2_N, DSI_1_D2_P, DSI_1_D3_N, DSI_1_D3_P
net class MDIO: (no net found under the mark)
net class RGMII_RX: (no net found under the mark)
net class RGMII_TX: (no net found under the mark)
differential pair; differential pair class USB2_SS; differential pair class USB: USB_2_SSRX_N, USB_2_SSRX_P, USB_2_SSTX_N, USB_2_SSTX_P

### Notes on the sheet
- 5 x 22uF/6.3V
- (near J1) Use 3.3V UART to USB cable
  (FTDI TTL-232R-3V3)
- (near J17) Use 1.8V UART to USB cable
  (FTDI TTL-232RG-VREG1V8-WE)
- standoffs for module - near pins - 7mm
- standoffs for heat sink - far from pins - 2.5mm

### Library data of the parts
C3 = 0753-Cap 3P-1206-1uF/100V/6A: as C67 on sheet 100_Power
C4-C8 = 2404-Cap-0402-22uF/6.3V: as C86 on sheet 100_Power
J1 = 000-Hdr-6pin: Header, 6-Pin; Note: PCB footprint only, no parts to buy or assemble
J17 = 000-Hdr-3pin: Header, 3-Pin; Note: PCB footprint only, no parts to buy or assemble
L2 = 1641-Fer-1206-600ohm/2.5A: as L8 on sheet 100_Power
L3 = 0405-Fer-0603-330ohm/1.7A: as L15 on sheet 400_USB1_OTG
M1 = 1140-Conn-Toradex-Verdin: (-55 to 85 DegC) CONN DDR4 SODIMM 260P 5.2H STD; Mfr: TE Connectivity; PN: 1140
ME1 ME2 = 1412-Post-M2-7mm: (-55 to 155 DegC) ROUND STANDOFF M2X0.4 STEEL 7MM for Verdin; Mfr: Wurth Electronics; PN: 1412
ME3 ME4 = 1141-Post-M2-2.5mm: (-55 to 155 DegC) ROUND STANDOFF M2X0.4 STEEL 2.5MM for Verdin; Mfr: Wurth Electronics; PN: 1141
Q15 = 1146-NTZD3154NT1G: (-55 to 150 DegC) MOSFET 2N-CH (dual) 20V 0.54A SOT-563 1.6x1.6mm Vth:1V Ron typ:400m@4.5V, 500m@2.5V, 700m@1.8V; Mfr: ON Semiconductor; PN: 1146; Alt: NTZD3154NT5G,PMDT290UNE,115
R4 = 1538-Res-0402-27k: as R36 on sheet 100_Power
R5 = 0195-Res-0603-0.0ohm: (-55 to 155 DegC) RES 0.0 OHM 1/10W JUMP 0603; Mfr: Samsung; MfrNo: RC1608J000CS; Alt: 311-0.0GRCT-ND; Alt2: A106051CT-ND; PN: 195; TR: 1276-3510-2-ND
R6 = 0000-Res-0603-DNP: RES 0603
R7 = 1650-Res-0402-1K: (-55 to 155 DegC AEC) RES 1K OHM 1% 1/16W 100ppm 0402; MfrNo: CRGCQ0402F1K0; Mfr: TE Connectivity; Alt: CR0402AFX-1001GLF,AC0402FR-131KL,AC0402FR-071KL; PN: 1650
R85 R224 = 1536-Res-0402-1.87K: as R40 on sheet 100_Power
R264 R269-R271 = 2233-Res-0402-4.7K: as R49 on sheet 100_Power
X2 = 000-TestPoint: as X1 on sheet 100_Power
